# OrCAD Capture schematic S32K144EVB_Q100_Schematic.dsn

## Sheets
1 4. OpenSDA interface: size D; title: S32K144EVB-Q100; rev: C; company: Freescale Semiconductor; note: SCH-29248 PDF: SPF-29248; note: 6501 William Cannon Drive West; note: Austin, TX 78735-8598
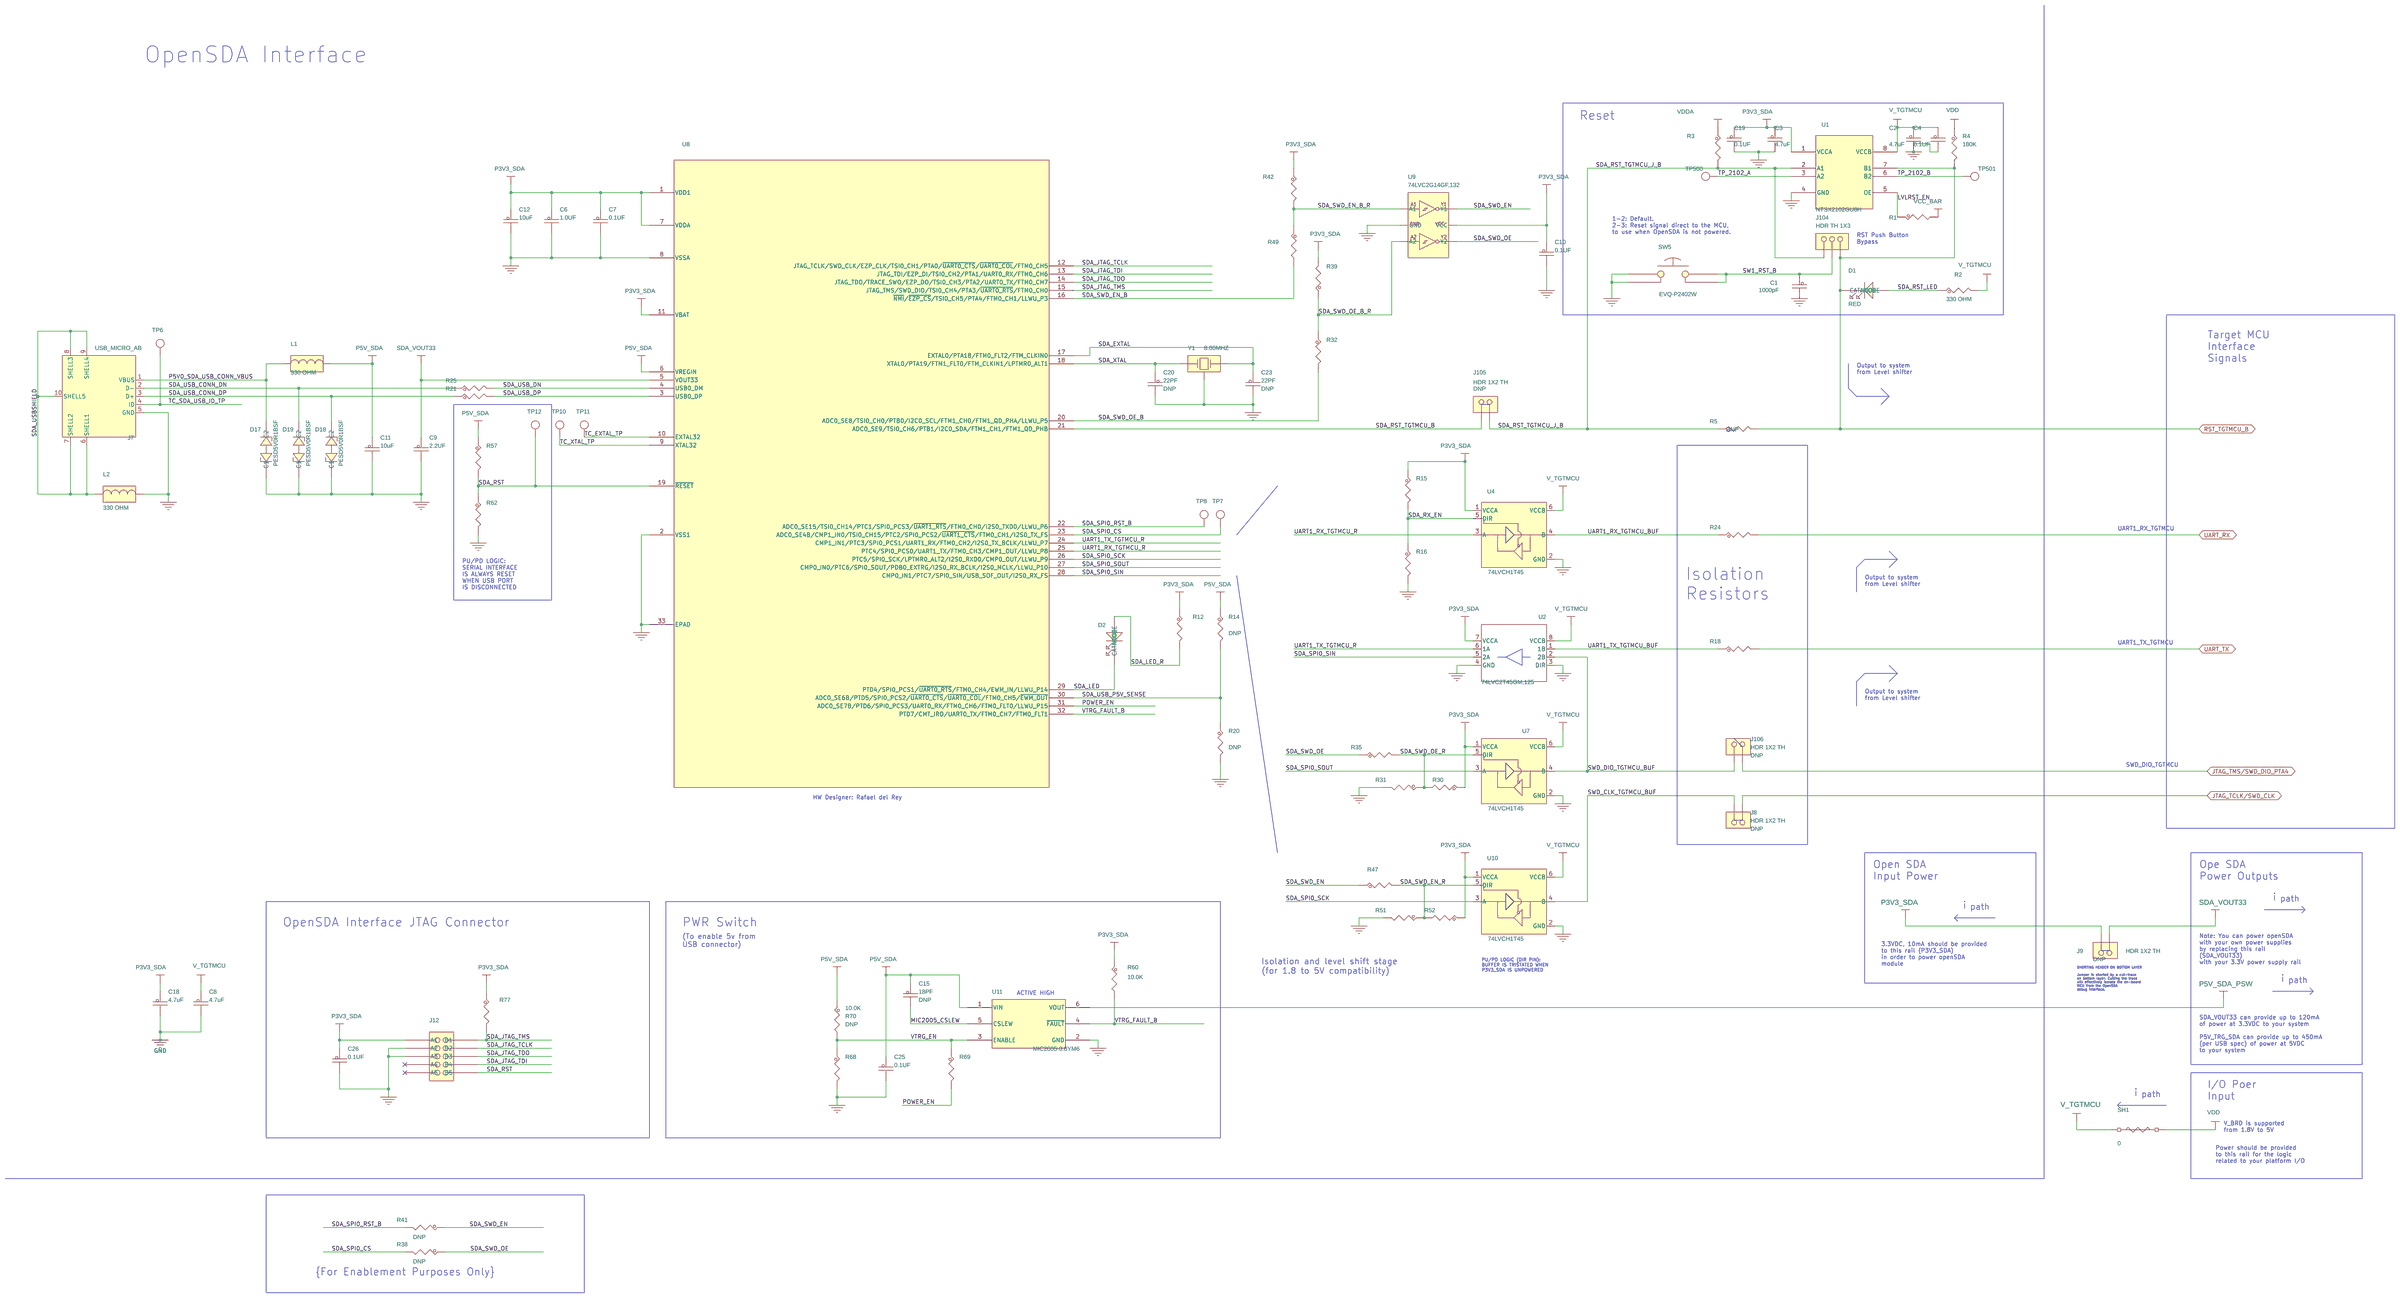
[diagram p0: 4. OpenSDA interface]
2 3. S32K144 MCU: size D; company: NXP Semiconductors
3 2. Notes and Block Diagram: company: NXP Semiconductors
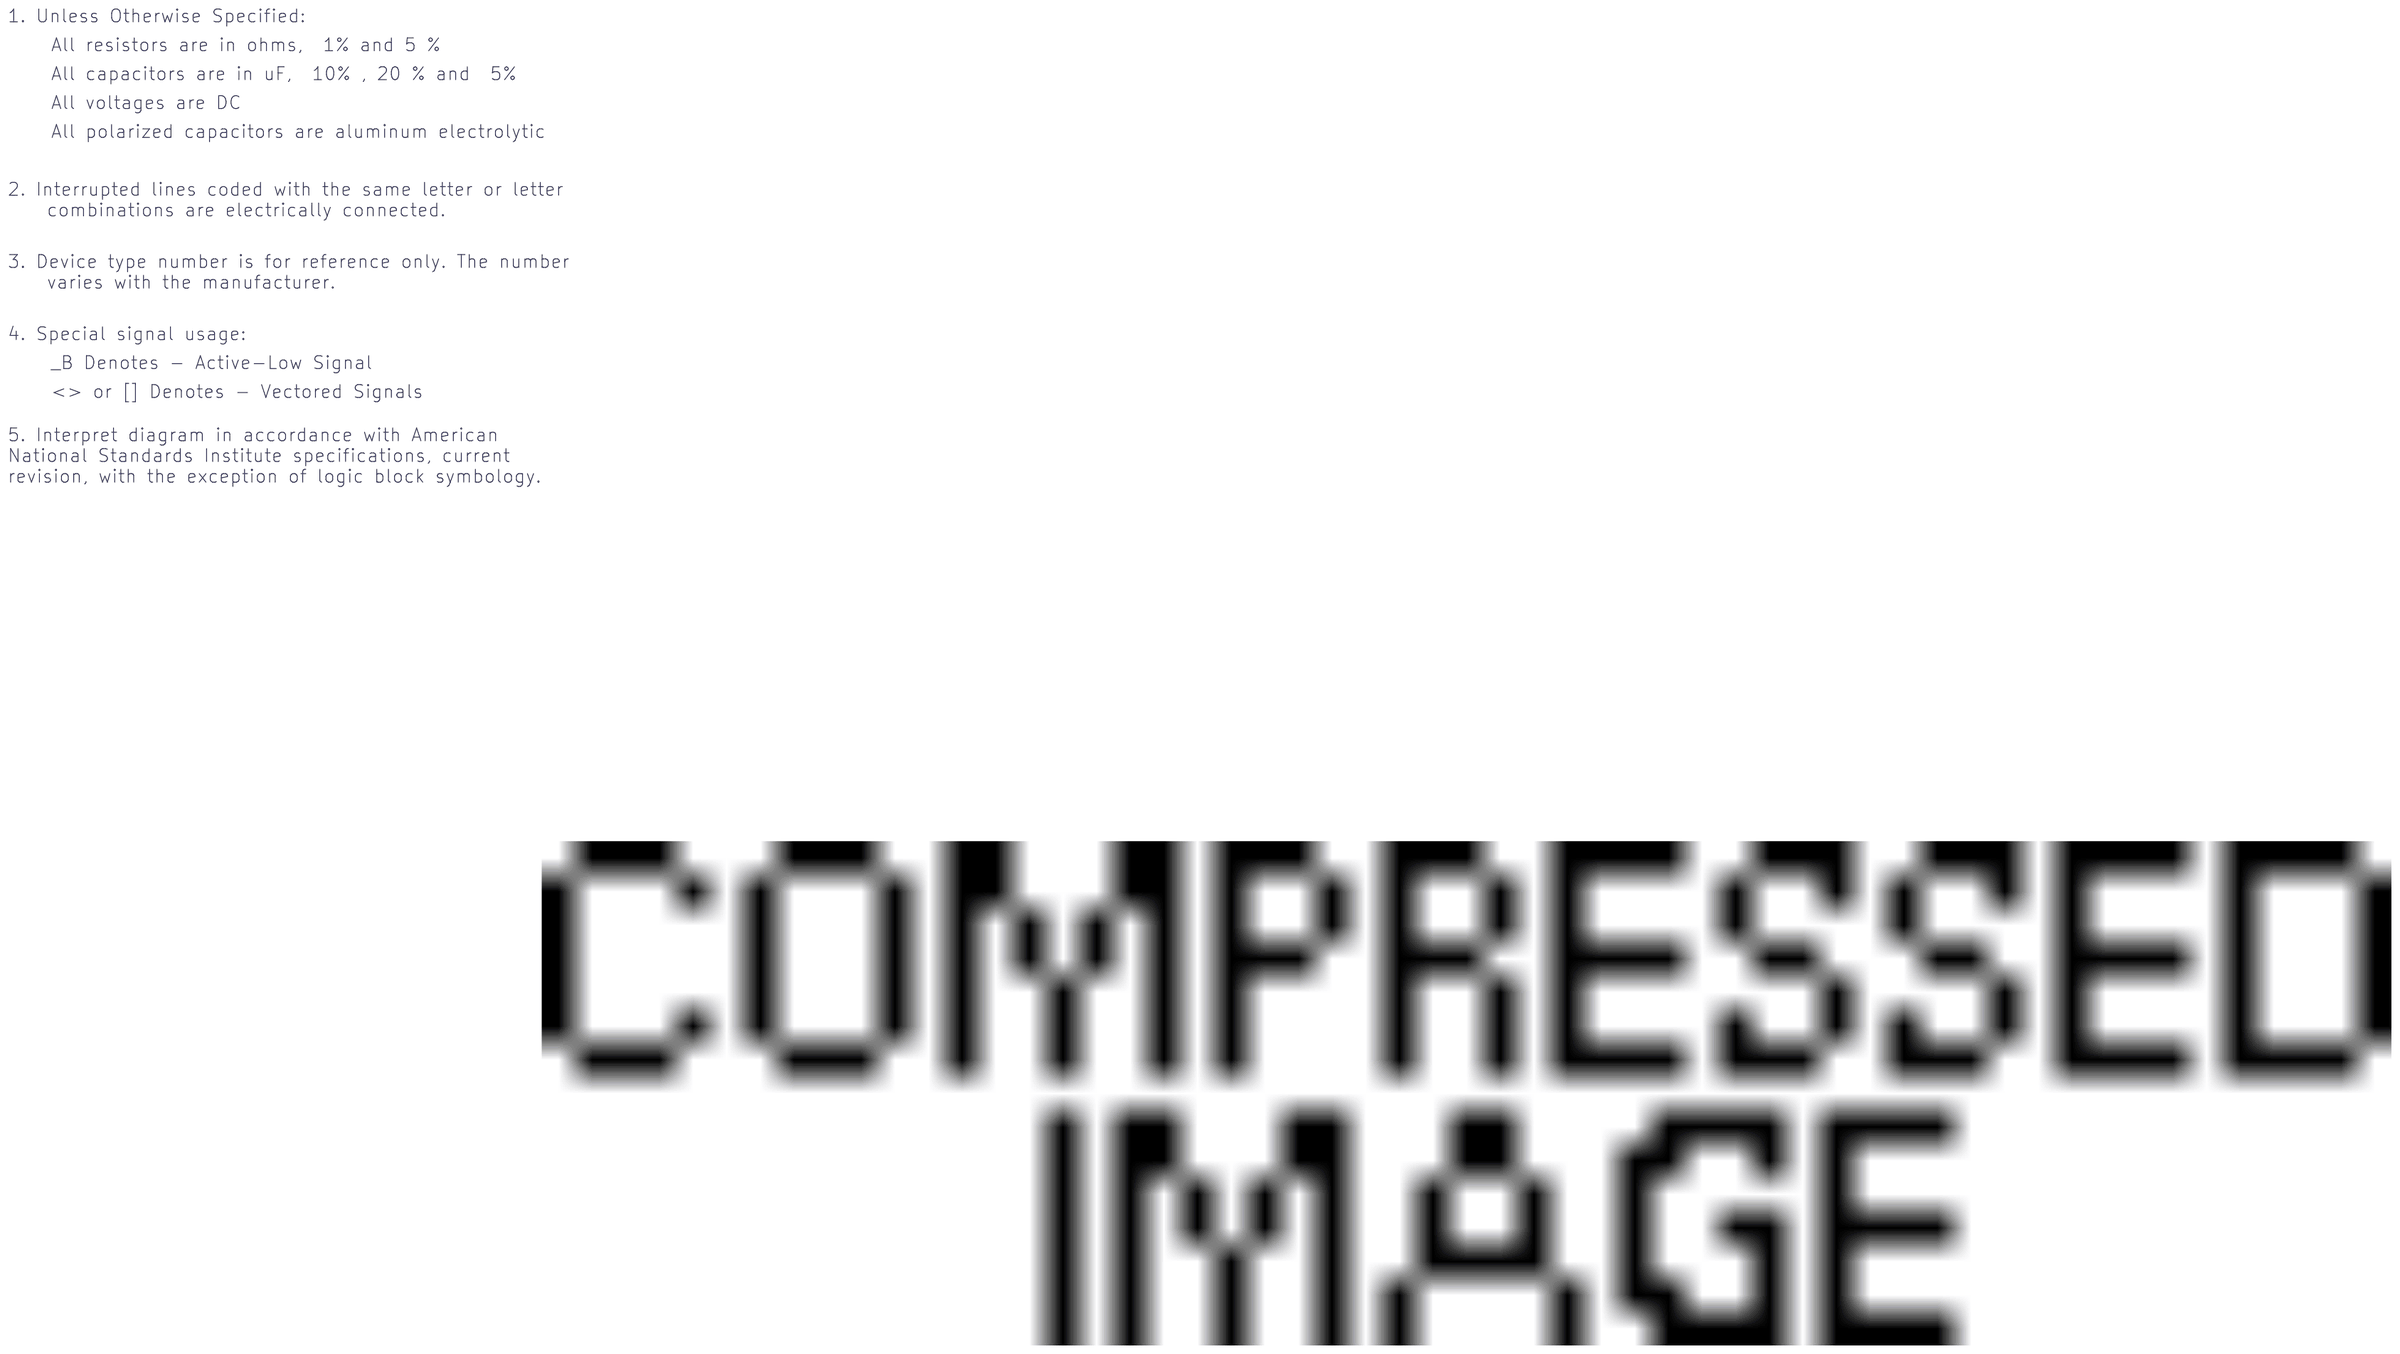
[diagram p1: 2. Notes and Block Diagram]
4 1. Title Page: company: NXP Semiconductors
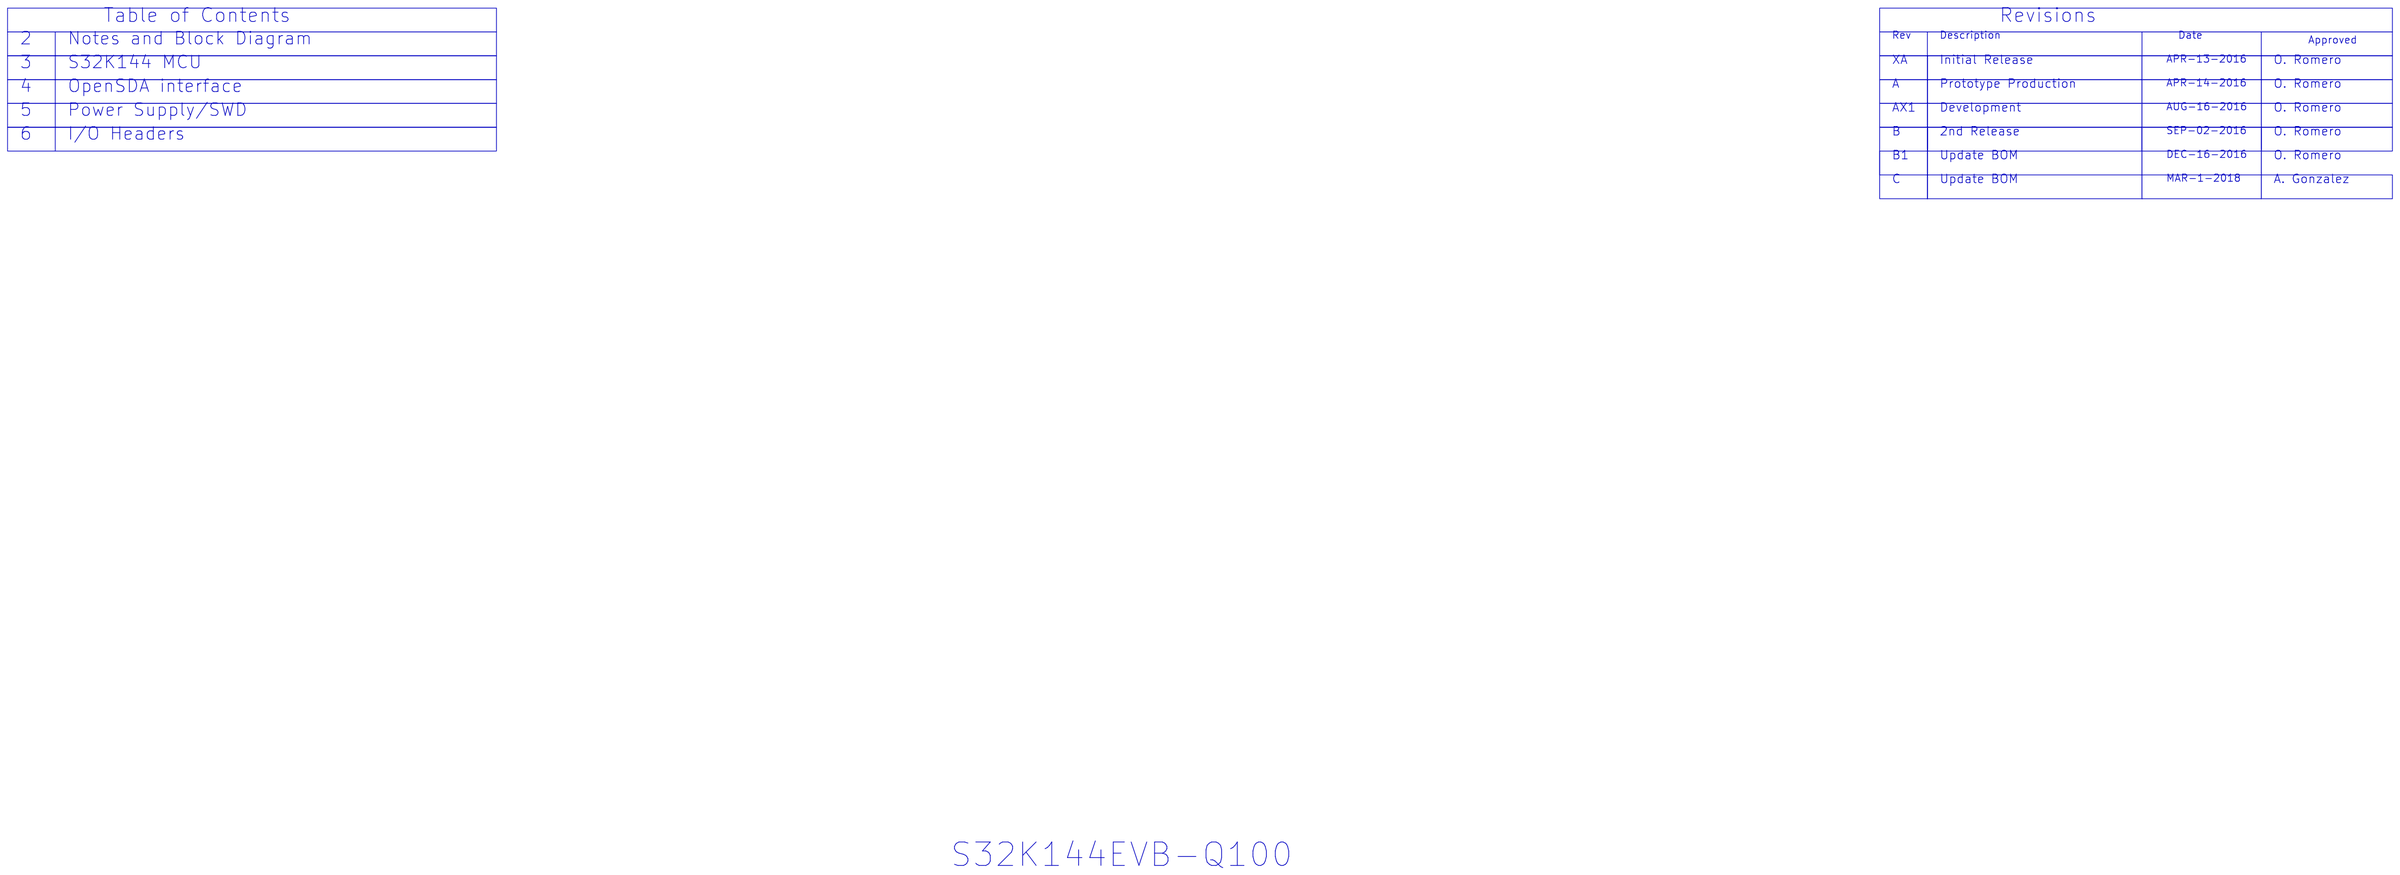
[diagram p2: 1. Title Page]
5 5. Power Supply/SWD: size C
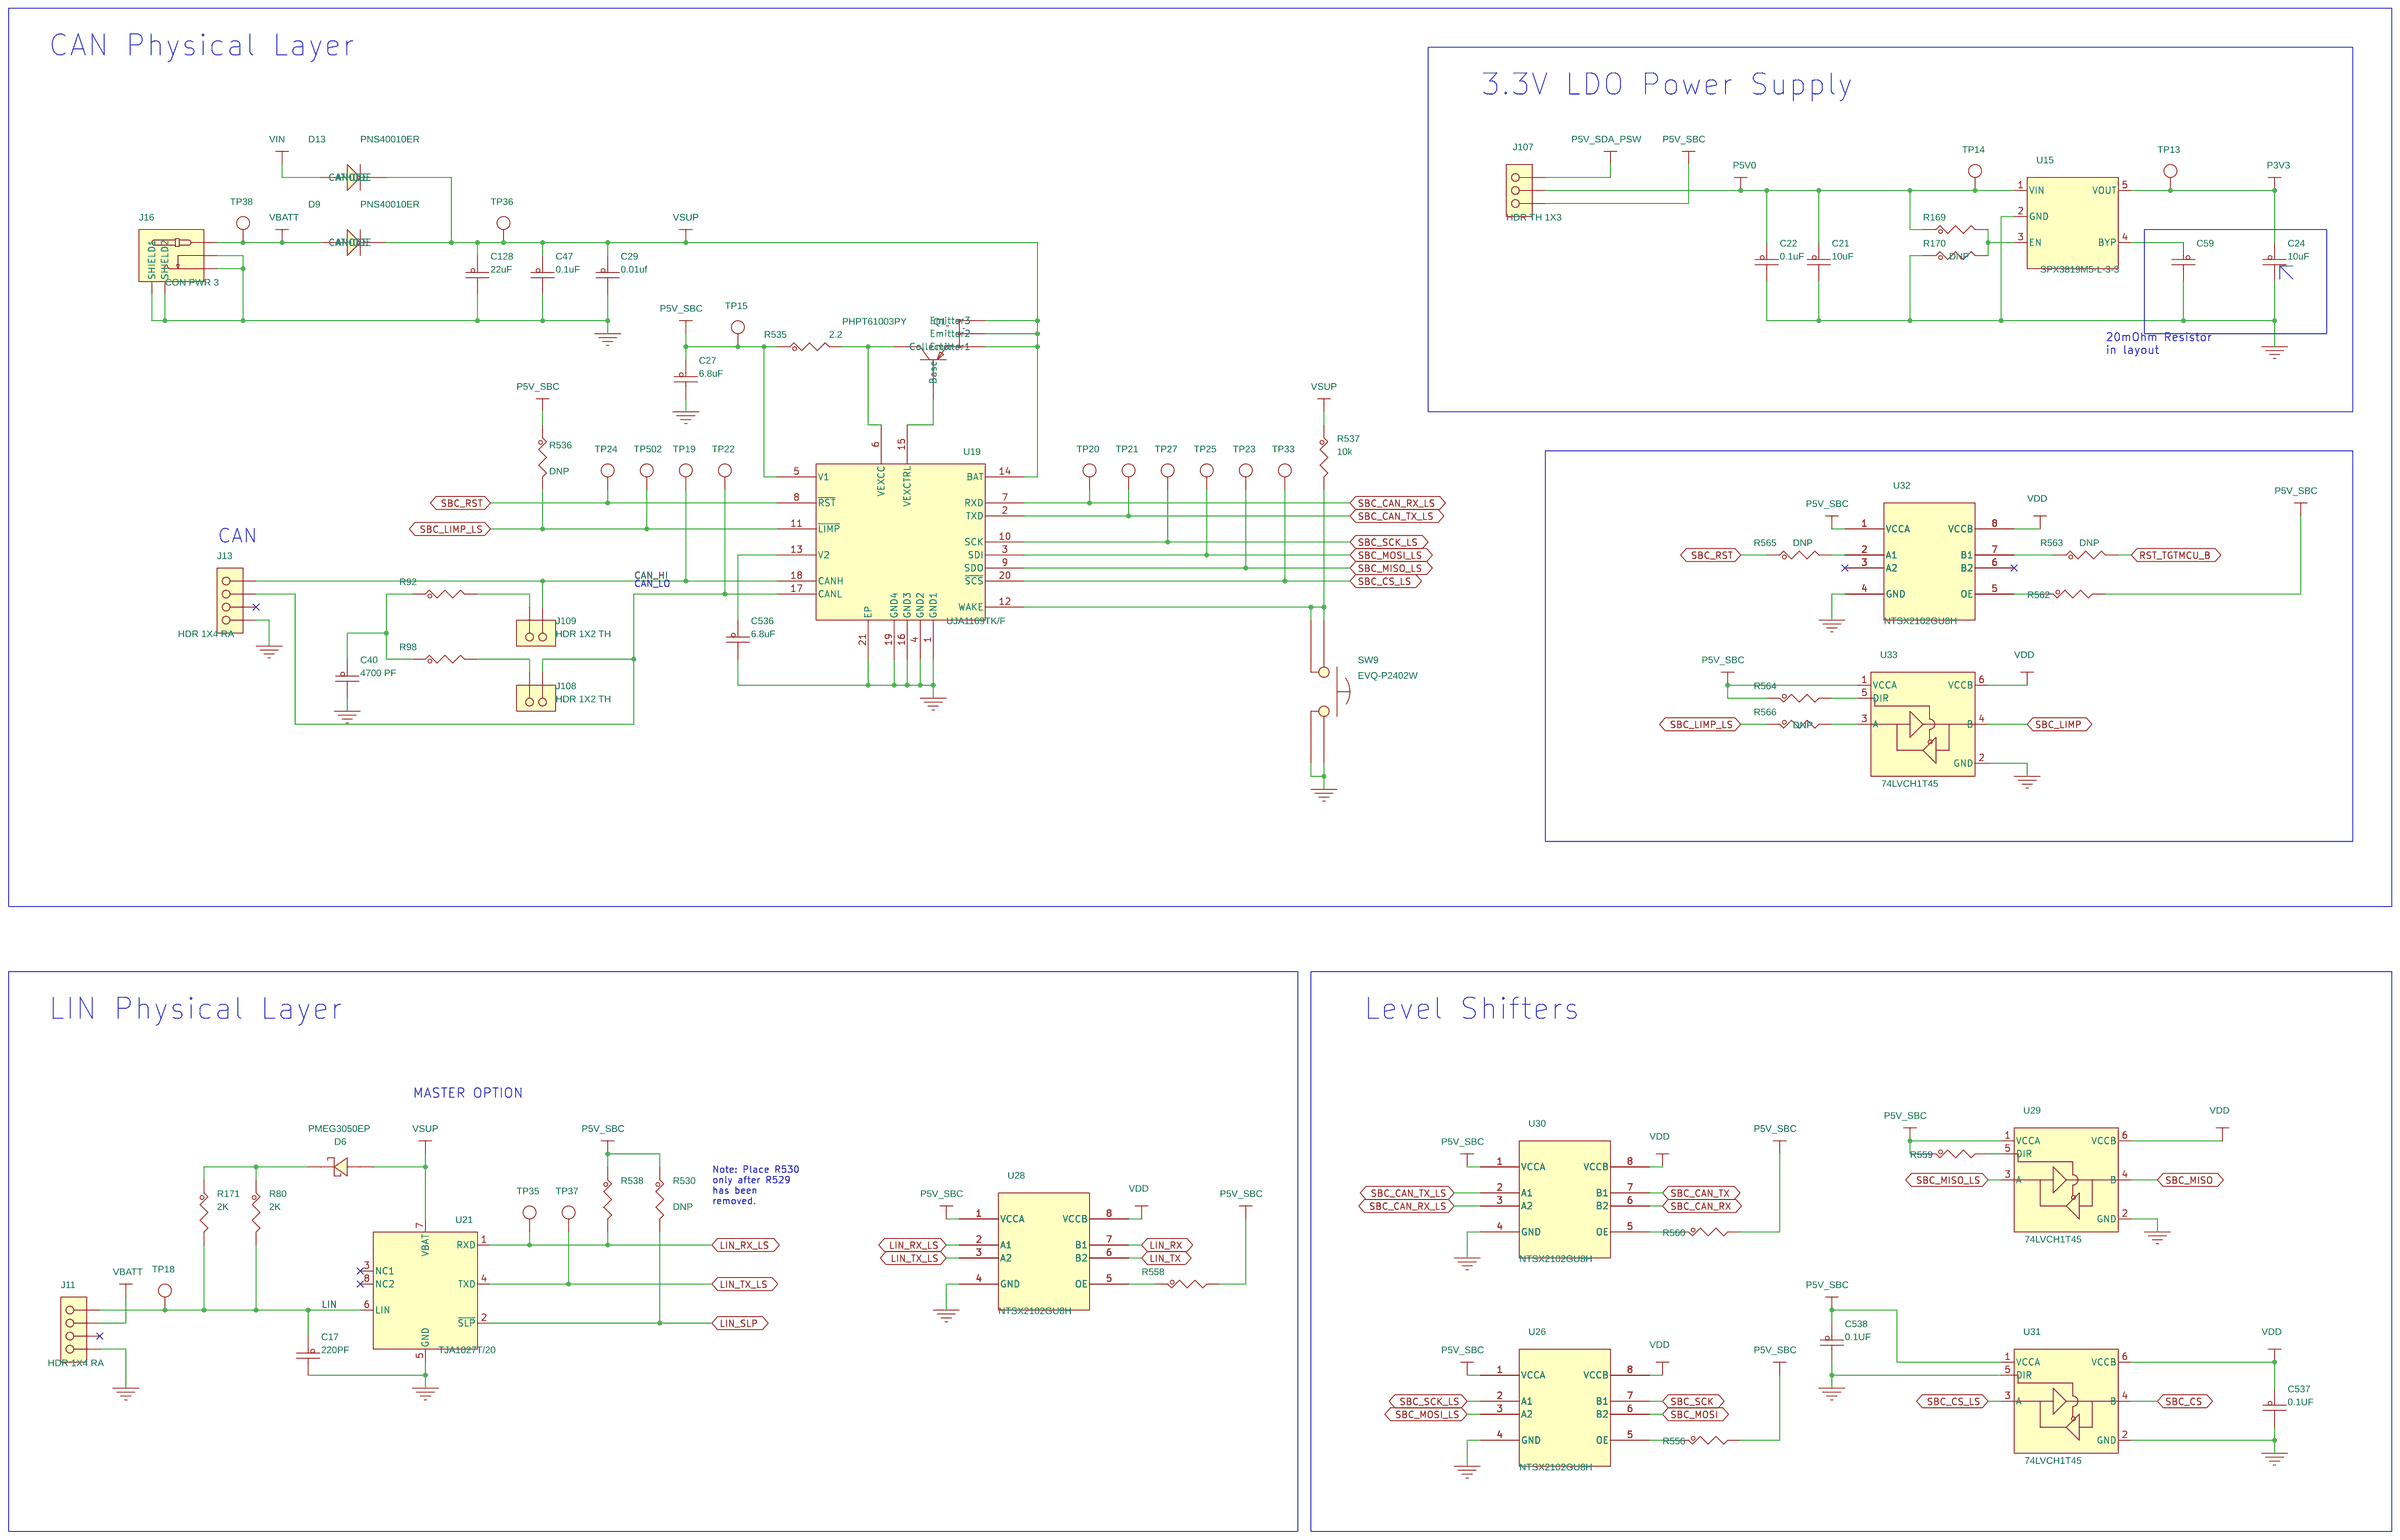
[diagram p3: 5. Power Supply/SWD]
6 6. I/O Headers: size C
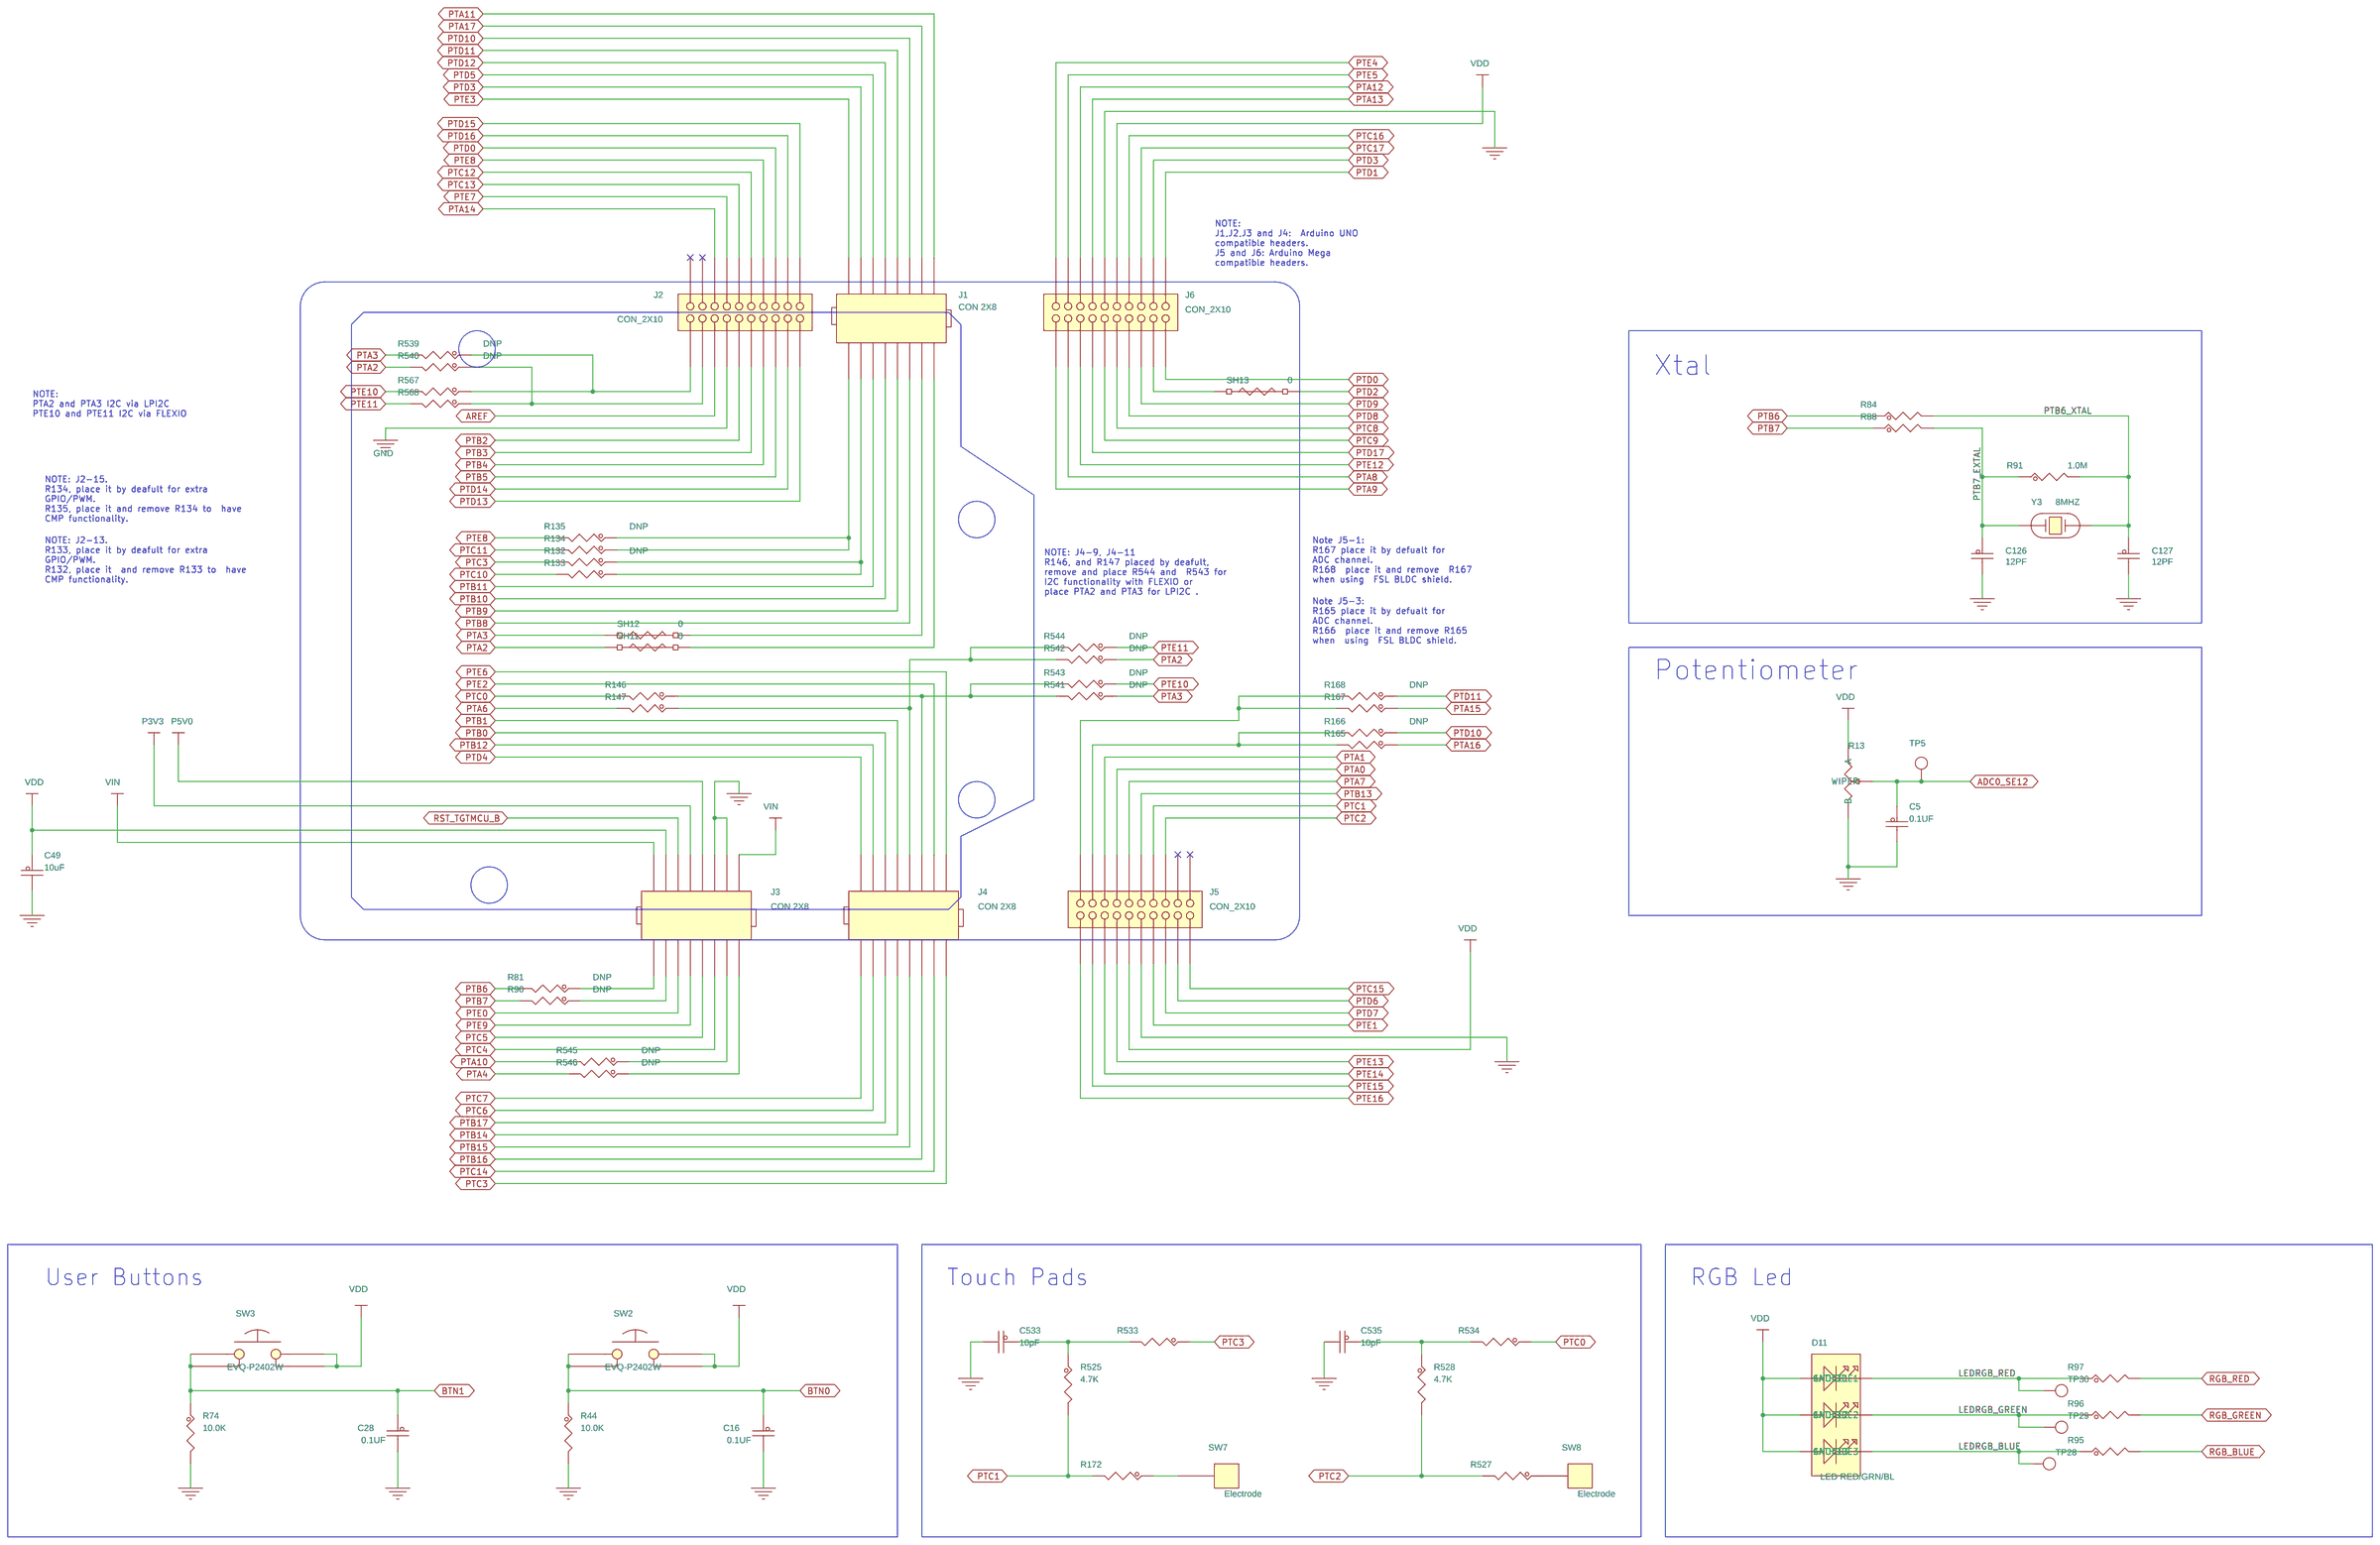
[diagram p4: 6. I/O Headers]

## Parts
sheet 3. S32K144 MCU
C43  10uF  [CC0603_OV]
C129  10uF  [CC0603_OV]
C131  10uF  [CC0603_OV]
C133  1UF  [CC0603_OV]
C137  1UF  [CC0603_OV]
C140  0.1uF  [CC0402_25]
C141  0.1uF  [CC0402_25]
C142  0.1uF  [CC0402_25]
C143  0.1uF  [CC0402_25]
C144  0.1uF  [CC0402_25]
C145  0.1uF  [CC0402_25]
C146  1UF  [CC0603_OV]
C147  1000PF  [CC0603_OV]
C148  0.1uF  [CC0402_25]
D3  GREEN  [LED_0603]
D7  BZX384-C30  [sod323]
J10  HDR TH 1X3  [HDR103]
J14  HDR 2X5  [CON_2RH_10_50]
J15  HDR 1X2 TH  [HDR102]
R56  330  [RC0603_OV]
R63  0  [RC0603_OV]
R64  0  [RC0603_OV]
R99  1K  [RC0603_OV]
R103  0  [RC0603_OV]
R109  0  [RC0603_OV]
R117  0  [RC0603_OV]
R119  0  [RC0603_OV]
R120  0  [RC0603_OV]
R121  10K  [RC0603_OV]
R122  0  [RC0603_OV]
R123  0  [RC0603_OV]
R124  0  [RC0603_OV]
R125  0  [RC0603_OV]
R126  0  [RC0603_OV]
R127  0  [RC0603_OV]
R128  0  [RC0603_OV]
R129  0  [RC0603_OV]
R130  0  [RC0603_OV]
R131  0  [RC0603_OV]
R136  0  [RC0603_OV]
R137  0  [RC0603_OV]
R152  0  [RC0603_OV]
R153  0  [RC0603_OV]
R154  0  [RC0603_OV]
R155  0  [RC0603_OV]
R156  0  [RC0603_OV]
R161  0  [RC0603_OV]
R162  0  [RC0603_OV]
R164  0  [RC0603_OV]
R529  0  [RC0603_OV]
R532  0  [RC0603_OV]
TP1  TEST POINT BLACK  [TEST_LOOP]
TP4  TEST POINT BLACK  [TEST_LOOP]
TP9  TEST POINT BLACK  [TEST_LOOP]
TP16  TEST POINT BLACK  [TEST_LOOP]
TP17  TEST POINT BLACK  [TEST_LOOP]
TP31  TPAD_030  [TPAD_030]
TP32  TEST POINT BLACK  [TEST_LOOP]
TP34  TPAD_030  [TPAD_030]
U17  PS32K144HFT0VLLT  [LQFP100_0P5_14X14]
sheet 4. OpenSDA interface
C1  1000pF  [CC0402_25]
C2  4.7uF  [CC0402_25]
C3  4.7uF  [CC0402_25]
C4  0.1UF  [CC0402_25]
C6  1.0UF  [CC0402_25]
C7  0.1UF  [CC0402_25]
C8  4.7uF  [CC0402_25]
C9  2.2UF  [CC0603_OV]
C10  0.1UF  [CC0402_25]
C11  10uF  [CC0402_25]
C12  10uF  [CC0603_OV]
C15  18PF  [CC0603_OV]
C18  4.7uF  [CC0402_25]
C19  0.1UF  [CC0402_25]
C20  22PF  [CC0402_25]
C23  22PF  [CC0402_25]
C25  0.1UF  [CC0402_25]
C26  0.1UF  [CC0402_25]
D1  RED  [LED_0603]
D2  LED GREEN  [LED_0603]
D17  PESD5V0R1BSF  [dsn0603-2]
D18  PESD5V0R1BSF  [dsn0603-2]
D19  PESD5V0R1BSF  [dsn0603-2]
J7  USB_MICRO_AB  [con_microab_10f_25_sm_ra]
J8  HDR 1X2 TH  [SH_HDR102_BOTTOM]
J9  HDR 1X2 TH  [SH_HDR102_BOTTOM]
J12  HDR 2X5  [CON_2RH_10_50]
J104  HDR TH 1X3  [HDR103]
J105  HDR 1X2 TH  [SH_HDR102_BOTTOM]
J106  HDR 1X2 TH  [SH_HDR102_BOTTOM]
L1  330 OHM  [ind_1608]
L2  330 OHM  [ind_1608]
R1  4.7K  [RC0402_25]
R2  330 OHM  [RC0402_25]
R3  10.0K  [RC0402_25]
R4  180K  [RC0402_25]
R5  0  [RC0402_25]
R12  220  [RC0603_OV]
R14  4.7K  [RC0402_25]
R15  4.7K  [RC0402_25]
R16  10.0K  [RC0402_25]
R18  0  [RC0402_25]
R20  10.0K  [RC0402_25]
R21  33  [RC0402_25]
R24  0  [RC0402_25]
R25  33  [RC0402_25]
R30  4.7K  [RC0402_25]
R31  10.0K  [RC0402_25]
R32  0  [RC0402_25]
R35  0  [RC0402_25]
R38  0  [RC0402_25]
R39  10.0K  [RC0402_25]
R41  0  [RC0402_25]
R42  10.0K  [RC0402_25]
R47  0  [RC0402_25]
R49  0  [RC0402_25]
R51  10.0K  [RC0402_25]
R52  4.7K  [RC0402_25]
R57  4.7K  [RC0402_25]
R60  10.0K  [RC0402_25]
R62  10.0K  [RC0402_25]
R68  15K  [RC0402_25]
R69  1.0K  [RC0402_25]
R70  10.0K  [RC0402_25]
R77  10.0K  [RC0402_25]
SH1  0  [SH0603]
SW5  EVQ-P2402W  [sw4_spst_4p8X3p6_2p5]
TP6  TPAD_030  [TPAD_030]
TP7  TPAD_030  [TPAD_030]
TP8  TPAD_030  [TPAD_030]
TP10  TPAD_030  [TPAD_030]
TP11  TPAD_030  [TPAD_030]
TP12  TPAD_030  [TPAD_030]
TP500  TPAD_030  [TPAD_030]
TP501  TPAD_030  [TPAD_030]
U1  NTSX2102GU8H  [xqfn8_1p45x1p25mm]
U2  74LVC2T45GM,125  [qfn8_1p6x1p6mm]
U4  74LVCH1T45  [udfn6_1x1p5mm]
U7  74LVCH1T45  [udfn6_1x1p5mm]
U8  MK20DX128VFM5  [QFN32_S142EP]
U9  74LVC2G14GF,132  [SOT891_6P_0P35_1P05X1P05]
U10  74LVCH1T45  [udfn6_1x1p5mm]
U11  MIC2005-0.8YM6  [SOT23-6_a]
Y1  8.00MHZ  [xtal3_3p35x1p45_sm]
sheet 5. Power Supply/SWD
C17  220PF  [CC0603_OV]
C21  10uF  [CC0603_OV]
C22  0.1uF  [CC0603_OV]
C24  10uF  [CC0603_OV]
C27  6.8uF  [CC0805_OV]
C29  0.01uf  [CC0603_OV]
C40  4700 PF  [CC0603_OV]
C47  0.1uF  [CC0603_OV]
C59  0.01UF  [CC0402_25]
C128  22uF  [CC0805_OV]
C536  6.8uF  [CC0805_OV]
C537  0.1UF  [CC0402_25]
C538  0.1UF  [CC0402_25]
D6  PMEG3050EP  [sod-128]
D9  PNS40010ER  [sod123w]
D13  PNS40010ER  [sod123w]
J11  HDR 1X4 RA  [con_hdr_4m_100_th_ra]
J13  HDR 1X4 RA  [con_hdr_4m_100_th_ra]
J16  CON PWR 3  [con3_pwr_jack_th_pj051a]
J107  HDR TH 1X3  [HDR103]
J108  HDR 1X2 TH  [HDR102]
J109  HDR 1X2 TH  [HDR102]
Q1  PHPT61003PY  [LFPAK5_1P27_5X4]
R80  2K  [RC0805_OV]
R92  60.4  [RC1206_OV]
R98  60.4  [RC1206_OV]
R169  0  [RC0402_25]
R170  0  [RC0402_25]
R171  2K  [RC0805_OV]
R530  4.7K  [RC0603_OV]
R535  2.2  [RC0805_OV]
R536  4.7K  [RC0603_OV]
R537  10k  [RC0805_OV]
R538  4.7K  [RC0603_OV]
R556  4.7K  [RC0402_25]
R558  4.7K  [RC0402_25]
R559  4.7K  [RC0402_25]
R560  4.7K  [RC0402_25]
R562  4.7K  [RC0402_25]
R563  0  [RC0603_OV]
R564  4.7K  [RC0402_25]
R565  0  [RC0603_OV]
R566  0  [RC0603_OV]
SW9  EVQ-P2402W  [sw4_spst_4p8X3p6_2p5]
TP13  TPAD_030  [TPAD_030]
TP14  TPAD_030  [TPAD_030]
TP15  TPAD_030  [TPAD_030]
TP18  TPAD_030  [TPAD_030]
TP19  TPAD_030  [TPAD_030]
TP20  TPAD_030  [TPAD_030]
TP21  TPAD_030  [TPAD_030]
TP22  TPAD_030  [TPAD_030]
TP23  TPAD_030  [TPAD_030]
TP24  TPAD_030  [TPAD_030]
TP25  TPAD_030  [TPAD_030]
TP27  TPAD_030  [TPAD_030]
TP33  TPAD_030  [TPAD_030]
TP35  TPAD_030  [TPAD_030]
TP36  TPAD_030  [TPAD_030]
TP37  TPAD_030  [TPAD_030]
TP38  TPAD_030  [TPAD_030]
TP502  TPAD_030  [TPAD_030]
U15  SPX3819M5-L-3-3  [SOT23_5S]
U19  UJA1169TK/F  [son20_0p5_3p6x5p6]
U21  TJA1027T/20  [so8_1p27_4x5]
U26  NTSX2102GU8H  [xqfn8_1p45x1p25mm]
U28  NTSX2102GU8H  [xqfn8_1p45x1p25mm]
U29  74LVCH1T45  [udfn6_1x1p5mm]
U30  NTSX2102GU8H  [xqfn8_1p45x1p25mm]
U31  74LVCH1T45  [udfn6_1x1p5mm]
U32  NTSX2102GU8H  [xqfn8_1p45x1p25mm]
U33  74LVCH1T45  [udfn6_1x1p5mm]
sheet 6. I/O Headers
C5  0.1UF  [CC0402_25]
C16  0.1UF  [CC0402_25]
C28  0.1UF  [CC0402_25]
C49  10uF  [CC0603_OV]
C126  12PF  [CC0402_25]
C127  12PF  [CC0402_25]
C533  10pF  [CC0603_OV]
C535  10pF  [CC0603_OV]
D11  LED RED/GRN/BL  [led6_5x6mm]
J1  CON 2X8  [con_skt2x8_th]
J2  CON_2X10  [con2x10_2p54_th]
J3  CON 2X8  [con_skt2x8_th]
J4  CON 2X8  [con_skt2x8_th]
J5  CON_2X10  [con2x10_2p54_th]
J6  CON_2X10  [con2x10_2p54_th]
R13  5K  [pot3_3352t]
R44  10.0K  [RC0402_25]
R74  10.0K  [RC0402_25]
R81  0  [RC0603_OV]
R84  0  [RC0603_OV]
R88  0  [RC0603_OV]
R90  0  [RC0603_OV]
R91  1.0M  [RC0603_OV]
R95  220  [RC0603_OV]
R96  220  [RC0603_OV]
R97  220  [RC0603_OV]
R132  0  [RC0603_OV]
R133  0  [RC0603_OV]
R134  0  [RC0603_OV]
R135  0  [RC0603_OV]
R146  0  [RC0603_OV]
R147  0  [RC0603_OV]
R165  0  [RC0603_OV]
R166  0  [RC0603_OV]
R167  0  [RC0603_OV]
R168  0  [RC0603_OV]
R172  0  [RC0603_OV]
R525  4.7K  [RC0603_OV]
R527  0  [RC0603_OV]
R528  4.7K  [RC0603_OV]
R533  0  [RC0603_OV]
R534  0  [RC0603_OV]
R539  0  [RC0603_OV]
R540  0  [RC0603_OV]
R541  0  [RC0603_OV]
R542  0  [RC0603_OV]
R543  0  [RC0603_OV]
R544  0  [RC0603_OV]
R545  0  [RC0603_OV]
R546  0  [RC0603_OV]
R567  0  [RC0603_OV]
R568  0  [RC0603_OV]
SH11  0  [SH0603]
SH12  0  [SH0603]
SH13  0  [SH0603]
SW2  EVQ-P2402W  [sw4_spst_4p8X3p6_2p5]
SW3  EVQ-P2402W  [sw4_spst_4p8X3p6_2p5]
SW7  Electrode  [electrode_sq_15mm]
SW8  Electrode  [electrode_sq_15mm]
TP5  TPAD_030  [TPAD_030]
TP28  TPAD_030  [TPAD_030]
TP29  TPAD_030  [TPAD_030]
TP30  TPAD_030  [TPAD_030]
Y3  8MHZ  [xtal2_3p3x2p6]

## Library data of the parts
C43 C49 C129 C131 = CAP_NP: CAP CER 10uF 10V 20% X7R 0603; AGILE_PN: 150-80120; CAD_APPROVED: Yes; FPLIST: CC0603_OV,CC0603,0603_CC; HEIGHT: 1MM; MFG_NAME01: MURATA; MFG_PN01: GRM188Z71A106MA73; ROHS: Yes; Temp_Range: -55°C to +125°C; Tolerance: 20%; VOLTAGE: 10V
C133 C137 C146 = CAP_NP: CAP CER 1.0UF 10V 10% X7R 0603; AGILE_PN: 150-78462; ASSY_OPT: DNP; CAD_APPROVED: Yes; FPLIST: CC0603_OV,CC0603,0603_CC; HEIGHT: 0.9MM; MFG_NAME01: MURATA; MFG_PN01: GRM188R71A105KA61D; ROHS: Yes; Tolerance: 10%; VOLTAGE: 10V
C140-C145 C148 = CAP_NP: CAP CER 0.1UF 10V 10% X7R 0402; AGILE_PN: 150-30217; CAD_APPROVED: Yes; FPLIST: CC0402_25,CC0402_HD,CC0402_SQ,0402_CC; HEIGHT: 0.55 MM; MFG_NAME01: SMEC; MFG_PN01: MCCB104K0NRTF; ROHS: Yes; Tolerance: 10%; VOLTAGE: 10V
C147 = CAP_NP: CAP CER 1000PF 100V 10% X7R 0603; AGILE_PN: 150-77156; ASSY_OPT: DNP; CAD_APPROVED: Yes; FPLIST: CC0603_OV,CC0603,0603_CC; HEIGHT: 0.95MM; MFG_NAME01: KEMET; MFG_PN01: C0603C102K1RACTU; ROHS: Yes; Tolerance: 10%; VOLTAGE: 100V
D3 = LED: LED GRN SGL 25MA 0603; AGILE_PN: 370-76549; CAD_APPROVED: Yes; HEIGHT: 0.85MM; MFG_NAME01: KINGBRIGHT; MFG_PN01: KPT-1608SGC; ROHS: Yes
D7 = ZDIODE: DIODE ZNR 30V 300mW SOD323; AGILE_PN: 480-78597; ASSY_OPT: DNP; CAD_APPROVED: Yes; HEIGHT: 1.1MM; MFG_NAME01: NEXPERIA; MFG_PN01: BZX384-C30,115; ROHS: Yes
J10 = CONN_HDR_3X1: HDR 1X3 TH 100MIL SP 339H AU 100L; AGILE_PN: 210-75726; ASSY_OPT: DNP; CAD_APPROVED: Yes; HEIGHT: 8.65MM; MFG_NAME01: SAMTEC; MFG_PN01: TSW-103-07-G-S; ROHS: Yes
J12 J14 = CONN_HDR_5X2: CONN,HEAD,2X5,STR,50/50 CON-2RH-10-50; AGILE_PN: 210-07961-00; CAD_APPROVED: Yes; FPLIST: CON_2RH_10_50,con_2rh_10_50_nsp; HEIGHT: 3.91 MM; MFG_NAME01: SAMTEC; MFG_PN01: FTS-105-01-F-D; ROHS: Yes
J15 = CONN_HDR_2X1: HDR 1X2 TH 100MIL SP 339H AU 98L; AGILE_PN: 210-75439; ASSY_OPT: DNP; CAD_APPROVED: YES; FPLIST: HDR102,SH_HDR102_BOTTOM; HEIGHT: 8.71 MM; MFG_NAME01: SAMTEC; MFG_PN01: TSW-102-07-G-S; ROHS: Yes
R56 = RES: RES MF 330 OHM 1/10W 1% 0603; AGILE_PN: 470-75512; CAD_APPROVED: Yes; FPLIST: RC0603_OV,RC0603,0603_CC; HEIGHT: 0.55 MM; MFG_NAME01: BOURNS; MFG_PN01: CR0603-FX-3300ELF; ROHS: Yes; Tolerance: 1%
R63 R81 R90 R109 R132 R135 R166 R168 R539-R546 R563 R565 R566 = RES: RES MF ZERO OHM 1/10W -- AEC-Q200 0603; AGILE_PN: 470-75407; ASSY_OPT: DNP; CAD_APPROVED: Yes; FPLIST: RC0603_OV,RC0603,R603-X2,0603_CC; HEIGHT: 0.6MM; MFG_NAME01: PANASONIC; MFG_PN01: ERJ-3GEY0R00V; ROHS: Yes; Tolerance: 1%
R64 R84 R88 R103 R117 R119 R120 R122-R131 R133 R134 R136 R137 R146 R147 R152-R156 R161 R162 R164 R165 R167 R172 R527 R529 R532-R534 R567 R568 = RES: RES MF ZERO OHM 1/10W -- AEC-Q200 0603; AGILE_PN: 470-75407; CAD_APPROVED: Yes; FPLIST: RC0603_OV,RC0603,R603-X2,0603_CC; HEIGHT: 0.6MM; MFG_NAME01: PANASONIC; MFG_PN01: ERJ-3GEY0R00V; ROHS: Yes; Tolerance: 1%
R99 = RES: RES MF 1.0K 1/10W 5% 0603; AGILE_PN: 470-75412; ASSY_OPT: DNP; CAD_APPROVED: YES; FPLIST: RC0603_OV,RC0603,0603_CC; HEIGHT: 0.6MM; MFG_NAME01: VENKEL COMPANY; MFG_PN01: CR0603-10W-102JT; ROHS: Yes; SIGNAL_MODEL: DEFAULT_RESISTOR_1000.000000OHM_2_1; Tolerance: 5%
R121 = RES: RES MF 10K 1/10W 0.1% AEC-Q200 0603; AGILE_PN: 470-80764; CAD_APPROVED: Yes; FPLIST: RC0603_OV,RC0603,0603_CC; HEIGHT: 0.55MM; MFG_NAME01: Vishay Intertechnology; MFG_PN01: TNPW060310K0BEEN; ROHS: Yes; Tolerance: 0.1%
TP1 TP4 TP9 TP16 TP17 TP32 = TestLoop: TEST POINT BLACK 40 MIL DRILL 180 MIL TH 109L; AGILE_PN: 210-75683; ASSY_OPT: DNP; CAD_APPROVED: Yes; HEIGHT: 4.8mm; MFG_NAME01: KEYSTONE ELECTRONICS; MFG_PN01: 5001; ROHS: Yes
TP5-TP8 TP10-TP15 TP18-TP25 TP27-TP31 TP33-TP38 TP500-TP502 = TestLoop: TEST POINT PAD 30MIL DIA SMT, NO PART TO ORDER; AGILE_PN: 211-76642; CAD_APPROVED: Yes; HEIGHT: 0.1MM; MFG_NAME01: NOTACOMPONENT; MFG_PN01: NOTACOMPONENT; ROHS: Yes
U17 = PS32K144_LQFP_3: IC MCU 512K FLASH 2.7-5.5V 112MHZ LQFP100; AGILE_PN: 344-02148; CAD_APPROVED: Yes; HEIGHT: 1.7 MM; MFG_NAME01: FREESCALE SEMICONDUCTOR; ROHS: Yes
C1 = CAP_NP: CAP CER 1000PF 50V 5% C0G 0402; AGILE_PN: 150-76334; CAD_APPROVED: Yes; FPLIST: CC0402_25,CC0402_HD,0402_CC; HEIGHT: 0.55MM; MFG_NAME01: MURATA; MFG_PN01: GRM1555C1H102JA01D; ROHS: Yes; Tolerance: 5%; VOLTAGE: 50V
C2 C3 C8 C18 = CAP_NP: CAP CER 4.7UF 6.3V 20% X5R 0402; AGILE_PN: 150-78463; CAD_APPROVED: Yes; FPLIST: CC0402_25,CC0402_HD,0402_CC; HEIGHT: 0.65MM; MFG_NAME01: TDK; MFG_PN01: C1005X5R0J475M050BC; PRIORITY_PN: 021-00169; ROHS: Yes; SIGNAL_MODEL: DEFAULT_CAPACITOR_4.7e+06pF_2_1; TOL: 10%; Tolerance: 20%; VOLTAGE: 6.3V
C4 C7 C10 C19 C25 C26 C537 C538 = CAP_NP: CAP CER 0.1UF 10V 10% X5R 0402; AGILE_PN: 150-75634; CAD_APPROVED: Yes; FPLIST: CC0402_25,CC0402_HD,0402_CC; HEIGHT: 0.64MM; MFG_NAME01: KEMET; MFG_PN01: C0402C104K8PAC; PRIORITY_PN: 021-00169; ROHS: Yes; SIGNAL_MODEL: DEFAULT_CAPACITOR_100000pF_2_1; TOL: 10%; Tolerance: 10%; VOLTAGE: 10V
C6 = CAP_NP: CAP CER 1.0UF 10V 10% X5R 0402; AGILE_PN: 150-75772; CAD_APPROVED: Yes; FPLIST: CC0402_25,CC0402_HD,0402_CC; HEIGHT: 0.6MM; MFG_NAME01: YAGEO AMERICA; MFG_PN01: CC0402KRX5R6BB105; PRIORITY_PN: 021-00242; ROHS: Yes; SIGNAL_MODEL: DEFAULT_CAPACITOR_1e+06pF_2_1; VOLTAGE: 10V
C9 = CAP_NP: CAP CER 2.2UF 10V 10% X7R 0603; AGILE_PN: 150-78564; CAD_APPROVED: Yes; FPLIST: CC0603_OV,CC0603,0603_CC; HEIGHT: 1.25MM; MFG_NAME01: TAIYO YUDEN; MFG_PN01: LMK107B7225KA-T; ROHS: Yes; SIGNAL_MODEL: DEFAULT_CAPACITOR_2.2e+06pF_2_1; Tolerance: 10%; VOLTAGE: 10V
C11 = CAP_NP: CAP CER 10uF 10V 20% X5R 0402; AGILE_PN: 150-79255; CAD_APPROVED: Yes; FPLIST: C0402_25,CC0402_HD,0402_CC; HEIGHT: 0.7MM; MFG_NAME01: NIC COMPONENTS CORP; MFG_PN01: NMC0402X5R106M10TRPF; PRIORITY_PN: 021-00242; ROHS: Yes; SIGNAL_MODEL: DEFAULT_CAPACITOR_1e+06pF_2_1; Tolerance: 20%; VOLTAGE: 10V
C12 = CAP_NP: CAP CER 10uF 16V 20% X5R 0603; AGILE_PN: 150-79092; CAD_APPROVED: Yes; FPLIST: CC0603_OV,CC0603,0603_CC; HEIGHT: 1mm; MFG_NAME01: TAIYO YUDEN; MFG_PN01: EMK107BBJ106MA-T; ROHS: Yes; SIGNAL_MODEL: DEFAULT_CAPACITOR_1e+07pF_2_1; TOL: 10%; Tolerance: 20%; VOLTAGE: 16V
C15 = CAP_NP: CAP CER 18PF 50V 5% C0G 0603; AGILE_PN: 150-75116; ASSY_OPT: DNP; CAD_APPROVED: Yes; FPLIST: CC0603_OV,CC0603,0603_CC; HEIGHT: 0.90MM; MFG_NAME01: YAGEO AMERICA; MFG_PN01: CC0603JRNPO9BN180; PRIORITY_PN: 021-00320; ROHS: Yes; SIGNAL_MODEL: DEFAULT_CAPACITOR_18.000000pF_2_1; TOL: 5%; Tolerance: 5%; VOLTAGE: 50V
C20 C23 = CAP_NP: CAP CER 22PF 50V 5% C0G 0402; AGILE_PN: 150-75266; ASSY_OPT: DNP; CAD_APPROVED: Yes; FPLIST: CC0402_25,CC0402_HD,0402_CC; HEIGHT: 0.635MM; MFG_NAME01: AVX; MFG_PN01: 04025A220JAT2A; PRIORITY_PN: 021-00234; ROHS: Yes; SIGNAL_MODEL: DEFAULT_CAPACITOR_22.000000pF_2_1; Tolerance: 5%; VOLTAGE: 50V
D1 = LED: LED ULTRA BRIGHT RED SGL 30MA 0603; AGILE_PN: 370-75079; CAD_APPROVED: Yes; HEIGHT: 0.9MM; MFG_NAME01: LITE ON; MFG_PN01: LTST-C190KRKT; ROHS: Yes
D2 = LED: LED GRN SGL 20MA 0603; AGILE_PN: 370-76565; CAD_APPROVED: Yes; HEIGHT: 0.67MM; MFG_NAME01: osram; MFG_PN01: LG L29K-G2J1-24-Z; ROHS: Yes
D17-D19 = DIODE_BIDIR: DIODE TVS 5VWM 9.2VC DSN0603-2; AGILE_PN: 480-79664; CAD_APPROVED: Yes; HEIGHT: 0.32MM; MFG_NAME01: NEXPERIA; MFG_PN01: PESD5V0R1BSFYL; ROHS: Yes
J7 = MICRO_USB_CONN_10PIN: CON 5 USB_MICRO_AB_RECEPTACLE RA SKT SMT 0.65MM SP 122H AU; AGILE_PN: 211-78945; CAD_APPROVED: Yes; HEIGHT: 3.1MM; MFG_NAME01: molex; MFG_PN01: 0475900001; ROHS: Yes
J8 J9 J105 J106 = CONN_HDR_2X1: HDR 1X2 TH 100MIL SP 339H AU 98L; AGILE_PN: 210-75439; ASSY_OPT: DNP; CAD_APPROVED: YES; FPLIST: HDR102,SH_HDR102_BOTTOM; HEIGHT: 8.71 MM; MFG_NAME01: SAMTEC; MFG_PN01: TSW-102-07-G-S; PRIORITY_PN: 028-00556; ROHS: Yes
J104 J107 = CONN_HDR_3X1: HDR 1X3 TH 100MIL SP 339H AU 100L; AGILE_PN: 210-75726; CAD_APPROVED: Yes; HEIGHT: 8.65MM; MFG_NAME01: SAMTEC; MFG_PN01: TSW-103-07-G-S; ROHS: Yes
L1 L2 = BEAD: IND FER BEAD 330OHM@100MHZ 1.7A 0603; AGILE_PN: 180-78156; CAD_APPROVED: Yes; FPLIST: ind_1608,0603_CC; HEIGHT: 0.95MM; MFG_NAME01: TDK; MFG_PN01: MPZ1608S331A; PART_TYPE: FERRITE\BEAD; ROHS: Yes; Tolerance: 25%
R1 R15 R30 R52 R57 R556 R558-R560 R562 R564 = RES: RES MF 4.7K 1/16W 5% 0402; AGILE_PN: 470-75626; CAD_APPROVED: Yes; FPLIST: RC0402_25,RC0402_HD,0402_CC; HEIGHT: 0.41mm; MFG_NAME01: NIC COMPONENTS CORP; MFG_PN01: NRCL04J472TRF; ROHS: Yes; SIGNAL_MODEL: DEFAULT_RESISTOR_4700OHM_2_1; TOL: 1%; Tolerance: 5%
R2 = RES: RES MF 330 OHM 1/16W 1% 0402; AGILE_PN: 470-80566; CAD_APPROVED: Yes; FPLIST: RC0402_25,RC0402_HD,0402_CC; HEIGHT: 0.4MM; MFG_NAME01: WALSIN TECHNOLOGY CORP.; MFG_PN01: WR04X3300FTL; ROHS: Yes; Tolerance: 1%
R3 R16 R31 R39 R42 R51 = RES: RES MF 10.0K 1/16W 1% AEC-Q200 0402; AGILE_PN: 470-75416; CAD_APPROVED: Yes; FPLIST: RC0402_25,RC0402_HD,0402_CC; HEIGHT: 0.4MM; MFG_NAME01: KOA SPEER; MFG_PN01: RK73H1ETTP1002F; PRIORITY_PN: 006-00552; ROHS: Yes; SIGNAL_MODEL: DEFAULT_RESISTOR_10000OHM_2_1; TOL: 5%; Tolerance: 1%
R4 = RES: RES MF 180K 1/10W 1% AEC-Q200 0402; AGILE_PN: 470-31088; CAD_APPROVED: Yes; FPLIST: RC0402_25,RC0402_HD,0402_CC; HEIGHT: 0.40 MM; MFG_NAME01: KOA SPEER; MFG_PN01: RK73H1ETTP1803F; ROHS: Yes; SIGNAL_MODEL: DEFAULT_RESISTOR_180000OHM_2_1; Temp_Range: -55C to +155C; Tolerance: 1%
R5 = RES: RES MF ZERO OHM 1/16W -- AEC-Q200 0402; AGILE_PN: 470-80742; ASSY_OPT: DNP; CAD_APPROVED: Yes; FPLIST: RC0402_25,RC0402_HD,0402_CC; HEIGHT: 0.45 MM; MFG_NAME01: VISHAY INTERTECHNOLOGY; MFG_PN01: CRCW04020000Z0ED; PRIORITY_PN: 006-00559; ROHS: Yes; SIGNAL_MODEL: DEFAULT_RESISTOR_0.001OHM_2_1; TOL: 5%; VOLTAGE: 1/16W
R12 = RES: RES MF 220 OHM 1/10W 5% 0603; AGILE_PN: 470-30297; CAD_APPROVED: Yes; FPLIST: RC0603_OV,RC0603,0603_CC; HEIGHT: 0.6MM; MFG_NAME01: YAGEO AMERICA; MFG_PN01: RC0603JR-07220RL; ROHS: Yes; SIGNAL_MODEL: DEFAULT_RESISTOR_220.000000OHM_2_1; Tolerance: 5%
R14 = RES: RES MF 4.7K 1/16W 5% 0402; AGILE_PN: 470-75626; ASSY_OPT: DNP; CAD_APPROVED: Yes; FPLIST: RC0402_25,RC0402_HD,0402_CC; HEIGHT: 0.41mm; MFG_NAME01: NIC COMPONENTS CORP; MFG_PN01: NRCL04J472TRF; ROHS: Yes; SIGNAL_MODEL: DEFAULT_RESISTOR_4700OHM_2_1; TOL: 1%; Tolerance: 5%
R18 R24 = RES: RES MF ZERO OHM 1/16W -- AEC-Q200 0402; AGILE_PN: 470-80742; CAD_APPROVED: Yes; FPLIST: RC0402_25,RC0402_HD,0402_CC; HEIGHT: 0.45 MM; MFG_NAME01: VISHAY INTERTECHNOLOGY; MFG_PN01: CRCW04020000Z0ED; PRIORITY_PN: 006-00559; ROHS: Yes; SIGNAL_MODEL: DEFAULT_RESISTOR_0.001OHM_2_1; TOL: 5%; VOLTAGE: 1/16W
R20 = RES: RES MF 10.0K 1/16W 1% AEC-Q200 0402; AGILE_PN: 470-75416; ASSY_OPT: DNP; CAD_APPROVED: Yes; FPLIST: RC0402_25,RC0402_HD,0402_CC; HEIGHT: 0.4MM; MFG_NAME01: KOA SPEER; MFG_PN01: RK73H1ETTP1002F; PRIORITY_PN: 006-00552; ROHS: Yes; SIGNAL_MODEL: DEFAULT_RESISTOR_10000OHM_2_1; Tolerance: 1%
R21 R25 = RES: RES MF 33.0 OHM 1/16W 1% 0402; AGILE_PN: 470-75790; CAD_APPROVED: Yes; FPLIST: RC0402_25,RC0402_HD,RC0402_X2,0402_CC; HEIGHT: 0.4MM; MFG_NAME01: THYE MING TECH CO LTD; MFG_PN01: CR-02FL6---33R; PRIORITY_PN: 006-00556; ROHS: Yes; SIGNAL_MODEL: DEFAULT_RESISTOR_33.000000OHM_2_1; Tolerance: 1%
R32 R35 R47 R49 = RES: RES MF ZERO OHM 1/16W -- AEC-Q200 0402; AGILE_PN: 470-80742; CAD_APPROVED: Yes; FPLIST: RC0402_25,RC0402_HD,0402_CC; HEIGHT: 0.45 MM; MFG_NAME01: VISHAY INTERTECHNOLOGY; MFG_PN01: CRCW04020000Z0ED; PRIORITY_PN: 006-00559; ROHS: Yes; SIGNAL_MODEL: DEFAULT_RESISTOR_0.001OHM_2_1; VOLTAGE: 1/16W
R38 R41 = RES: RES MF ZERO OHM 1/16W -- AEC-Q200 0402; AGILE_PN: 470-80742; ASSY_OPT: DNP; CAD_APPROVED: Yes; FPLIST: RC0402_25,RC0402_HD,0402_CC; HEIGHT: 0.45 MM; MFG_NAME01: VISHAY INTERTECHNOLOGY; MFG_PN01: CRCW04020000Z0ED; PRIORITY_PN: 006-00559; ROHS: Yes; SIGNAL_MODEL: DEFAULT_RESISTOR_0.001OHM_2_1; VOLTAGE: 1/16W
R44 R60 R74 = RES: RES MF 10.0K 1/16W 1% AEC-Q200 0402; AGILE_PN: 470-75416; CAD_APPROVED: Yes; FPLIST: RC0402_25,RC0402_HD,0402_CC; HEIGHT: 0.4MM; MFG_NAME01: KOA SPEER; MFG_PN01: RK73H1ETTP1002F; PRIORITY_PN: 006-00552; ROHS: Yes; SIGNAL_MODEL: DEFAULT_RESISTOR_10000OHM_2_1; TOL: 1%; Tolerance: 1%
R62 R77 = RES: RES MF 10.0K 1/16W 1% AEC-Q200 0402; AGILE_PN: 470-75416; CAD_APPROVED: Yes; FPLIST: RC0402_25,RC0402_HD,0402_CC; HEIGHT: 0.4MM; MFG_NAME01: KOA SPEER; MFG_PN01: RK73H1ETTP1002F; PRIORITY_PN: 006-00552; ROHS: Yes; SIGNAL_MODEL: DEFAULT_RESISTOR_10000OHM_2_1; Tolerance: 1%
R68 = RES: RES MF 15K  1/16W 1% 0402; AGILE_PN: 470-30965; CAD_APPROVED: Yes; FPLIST: RC0402_25,RC0402_HD,0402_CC; HEIGHT: 0.40 MM; MFG_NAME01: WALSIN TECHNOLOGY CORP.; MFG_PN01: WR04X1502FTL; ROHS: Yes; SIGNAL_MODEL: DEFAULT_RESISTOR_15000OHM_2_1; TOL: 1%; Tolerance: 1%
R69 = RES: RES MF 1.0K 1/16W 1% 0402; AGILE_PN: 470-76037; CAD_APPROVED: Yes; FPLIST: RC0402_25,RC0402_HD,RC0402_X2,0402_CC; HEIGHT: 0.4MM; MFG_NAME01: YAGEO AMERICA; MFG_PN01: RC0402FR-071KL; PRIORITY_PN: 006-00553; ROHS: Yes; SIGNAL_MODEL: DEFAULT_RESISTOR_1000.000000OHM_2_1; TOL: 1%; Tolerance: 1%; VOLTAGE: 1/16W
R70 = RES: RES MF 10.0K 1/16W 1% AEC-Q200 0402; AGILE_PN: 470-75416; ASSY_OPT: DNP; CAD_APPROVED: Yes; FPLIST: RC0402_25,RC0402_HD,0402_CC; HEIGHT: 0.4MM; MFG_NAME01: KOA SPEER; MFG_PN01: RK73H1ETTP1002F; PRIORITY_PN: 006-00552; ROHS: Yes; SIGNAL_MODEL: DEFAULT_RESISTOR_10000OHM_2_1; TOL: 1%; Tolerance: 1%
SH1 SH11-SH13 = RES_SHORT-2: ZERO OHM CUT TRACE 0603 PADS; NO PART TO ORDER; AGILE_PN: 470-80018; CAD_APPROVED: Yes; FPLIST: SH0603,SH0603_CC,SH0603-X2_PIN1TO2,SH0603-X2_PIN2TO3; HEIGHT: 0.1MM; MFG_NAME01: LAYOUT ELEMENT ONLY; MFG_PN01: LAYOUT ELEMENT ONLY; ROHS: Yes; SIGNAL_MODEL: DEFAULT_RESISTOR_0.001OHM_2_1
SW2 SW3 SW5 SW9 = EDGE_MOUNT_PB_SW_2: SW SPST PB NO 0.02A 15V SMT; AGILE_PN: 510-77992; CAD_APPROVED: Yes; HEIGHT: 2.7 MM; MFG_NAME01: Panasonic; ROHS: Yes
U1 U26 U28 U30 U32 = NTSX2102GU8H_8P: IC DUAL SUPPLY XCVR 50 MBPS 5.5V XQFN8; AGILE_PN: 312-80763; CAD_APPROVED: Yes; HEIGHT: 0.5MM; MFG_NAME01: NXP Semiconductors; ROHS: Yes; VOLTAGE: 5.5V
U2 = 74LVC2T45GM_8P: IC XCVR DUAL SUPPLY 1.2 -5.5V XQFN8; AGILE_PN: 312-80762; CAD_APPROVED: Yes; HEIGHT: 0.5MM; MFG_NAME01: NEXPERIA; ROHS: Yes; VOLTAGE: 5.5V
U4 U7 U10 U29 U31 U33 = 74LVCH1T45_6P: IC XCVR 1BIT 3-STATE DUAL 1.2-5.5V XSON6; AGILE_PN: 312-80758; CAD_APPROVED: Yes; HEIGHT: 0.5MM; MFG_NAME01: NEXPERIA; MFG_PN01: 74LVCH1T45GM,132; ROHS: Yes; VOLTAGE: 1.2-5.5V
U8 = PK20DX128V_QFN_32P: IC MCU FLASH 128KB 50MHZ 1.71-3.6V QFN32; AGILE_PN: 344-01231; CAD_APPROVED: Yes; HEIGHT: 1MM; MFG_NAME01: FREESCALE SEMICONDUCTOR; ROHS: Yes; VOLTAGE: 1.71-3.6V
U9 = NC7WP14: IC DUAL INV SCHMITT-TRIG 1.65-5.5V  XSON6; AGILE_PN: 315-80930; CAD_APPROVED: Yes; HEIGHT: 0.5MM; MFG_NAME01: NEXPERIA; ROHS: Yes
U11 = MIC2005-0.8YM6: IC LIN SW PWR 0.8A 2.5-5.5V SOT23-6; AGILE_PN: 315-79199; CAD_APPROVED: Yes; HEIGHT: 1.45MM; MFG_NAME01: MICREL; PRIORITY_PN: 051-MIC2005-08; ROHS: Yes; VOLTAGE: 2.5-5.5V
Y1 = XTAL_CS: XTAL 8.00MHZ RSN CERAMIC -- SMT; AGILE_PN: 230-77664; CAD_APPROVED: Yes; HEIGHT: 0.8MM; MFG_NAME01: MURATA; MFG_PN01: CSTCE8M00G55-R0; PRIORITY_PN: 048-00290; ROHS: Yes
C17 = CAP_NP: CAP CER 220PF 50V 10% X7R 0603; AGILE_PN: 150-75200; CAD_APPROVED: Yes; FPLIST: CC0603_OV,CC0603,0603_CC; HEIGHT: 0.9652MM; MFG_NAME01: KEMET; MFG_PN01: C0603C221K5RAC; ROHS: Yes; Tolerance: 10%; VOLTAGE: 50V
C21 = CAP_NP: CAP CER 10uF 25V 20% X5R 0603; AGILE_PN: 150-79272; CAD_APPROVED: Yes; FPLIST: CC0603_OV,CC0603,0603_CC; HEIGHT: 1MM; MFG_NAME01: Murata; MFG_PN01: GRM188R61E106MA73D; ROHS: Yes; SIGNAL_MODEL: DEFAULT_CAPACITOR_1e+07pF_2_1; Tolerance: 20%; VOLTAGE: 25V
C22 = CAP_NP: CAP CER 0.1uF 50V 10% X7R AEC-Q200 0603; AGILE_PN: 150-79042; CAD_APPROVED: Yes; FPLIST: CC0603_OV,CC0603,0603_CC; HEIGHT: 0.9 MM; MFG_NAME01: MURATA; MFG_PN01: GCM188R71H104KA57D; ROHS: Yes; Tolerance: 10%; VOLTAGE: 50V
C24 = CAP_NP: CAP CER 10uF 16V 20% X5R 0603; AGILE_PN: 150-79092; CAD_APPROVED: Yes; FPLIST: CC0603_OV,CC0603,0603_CC; HEIGHT: 1mm; MFG_NAME01: TAIYO YUDEN; MFG_PN01: EMK107BBJ106MA-T; ROHS: Yes; SIGNAL_MODEL: DEFAULT_CAPACITOR_1e+07pF_2_1; Tolerance: 20%; VOLTAGE: 16V
C27 C536 = CAP_NP: CAP CER 6.8uF 16V 10% X7S AEC-Q200 0805; AGILE_PN: 150-79536; CAD_APPROVED: Yes; FPLIST: CC0805_OV,CC0805,0805_CC; HEIGHT: 1.45MM; MFG_NAME01: TDK; MFG_PN01: CGA4J1X7S1C685K125AC; ROHS: Yes; Tolerance: 10%; VOLTAGE: 16V
C29 = CAP_NP: CAP CER 0.01uF 50V 10% X7R AEC-Q200 0603; AGILE_PN: 150-79361; CAD_APPROVED: Yes; FPLIST: CC0603_OV,CC0603,0603_CC; HEIGHT: 0.9MM; MFG_NAME01: TDK; MFG_PN01: CGA3E2X7R1H103K080AA; ROHS: Yes; Tolerance: 10%; VOLTAGE: 50V
C40 = CAP_NP: CAP CER 4700PF 50V 5% X7R 0603; AGILE_PN: 150-30045; CAD_APPROVED: Yes; FPLIST: CC0603_OV,CC0603,0603_CC; HEIGHT: 1.0MM; MFG_NAME01: AVX; MFG_PN01: 06035C472JAT2A; ROHS: Yes; Tolerance: 5%; VOLTAGE: 50V
C47 = CAP_NP: CAP CER 0.1uF 25V 10% X8R 0603; AGILE_PN: 150-78955; CAD_APPROVED: Yes; FPLIST: CC0603_OV,CC0603,0603_CC; HEIGHT: 0.9 MM; MFG_NAME01: TDK; MFG_PN01: C1608X8R1E104K080AA; ROHS: Yes; Temp_Range: -55 C to +150 C; Tolerance: 10%; VOLTAGE: 25V
C59 = CAP_NP: CAP CER 0.01UF 16V 20% X7R 0402; AGILE_PN: 150-30082; CAD_APPROVED: Yes; FPLIST: CC0402_25,CC0402_HD,0402_CC; HEIGHT: 0.56MM; MFG_NAME01: AVX; MFG_PN01: 0402YC103MAT2A; ROHS: Yes; TOL: 20%; Tolerance: 20%; VOLTAGE: 16V
C128 = CAP_NP: CAP CER 22uF 25V 20% X5R AEC-Q200 0805; AGILE_PN: 150-79697; CAD_APPROVED: Yes; FPLIST: CC0805_OV,CC0805,0805_CC; HEIGHT: 1.45MM; MFG_NAME01: MURATA; MFG_PN01: GRT21BR61E226ME13; ROHS: Yes; Tolerance: 20%; VOLTAGE: 25V
D6 = DIODE_SCHTKY: DIODE SCH RECT 5A 30V AEC-Q101 SOD128; AGILE_PN: 480-78776; CAD_APPROVED: Yes; HEIGHT: 1.1 MM; MFG_NAME01: NEXPERIA; MFG_PN01: PMEG3050EP,115; ROHS: Yes
D9 D13 = DIODE: DIODE RECT SW 1A 400V AEC-Q101 SOD123W; AGILE_PN: 480-79648; CAD_APPROVED: Yes; HEIGHT: 1.1MM; MFG_NAME01: NEXPERIA; MFG_PN01: PNS40010ER,115; ROHS: Yes
J11 J13 = CONN_HDR_4X1: HDR 1X4 TH RA 100MIL SP 268H AU 124L; AGILE_PN: 210-79929; CAD_APPROVED: Yes; HEIGHT: 6.81MM; MFG_NAME01: MOLEX; MFG_PN01: 0022122041; ROHS: Yes
J16 = DC_POWER_JACK_SHD: CON 3 PWR JACK RA TH 295H -- NI 98L; AGILE_PN: 210-79945; CAD_APPROVED: Yes; HEIGHT: 7.5MM; MFG_NAME01: CUI INC; MFG_PN01: PJ-051A; ROHS: Yes
J108 J109 = CONN_HDR_2X1: HDR 1X2 TH 100MIL SP 339H AU 98L; AGILE_PN: 210-75439; CAD_APPROVED: YES; FPLIST: HDR102,SH_HDR102_BOTTOM; HEIGHT: 8.71 MM; MFG_NAME01: SAMTEC; MFG_PN01: TSW-102-07-G-S; ROHS: Yes
Q1 = PMOS_5P: TRAN PNP PWR 3A 100V AEC-Q101 LFPAK56; AGILE_PN: 480-79653; CAD_APPROVED: Yes; HEIGHT: 1.2 MM; MFG_NAME01: NEXPERIA; MFG_PN01: PHPT61003PYX; ROHS: Yes
R80 R171 = RES: RES MF 2K 1/8W 1% 0805; AGILE_PN: 470-76341; CAD_APPROVED: Yes; FPLIST: RC0805_OV,RC0805,0805_CC; HEIGHT: 0.65MM; MFG_NAME01: BOURNS; MFG_PN01: CR0805-FX-2001ELF; ROHS: Yes; Tolerance: 1%
R92 R98 = RES: RES MF 60.4 OHM 1/4W 1% 1206; AGILE_PN: 470-78243; CAD_APPROVED: Yes; FPLIST: RC1206_OV,RC1206,1206_CC; HEIGHT: 0.6MM; MFG_NAME01: VISHAY INTERTECHNOLOGY; MFG_PN01: CRCW120660R4FKEA; ROHS: Yes; Tolerance: 1%
R169 = RES: RES MF ZERO OHM 1/16W -- AEC-Q200 0402; AGILE_PN: 470-80742; CAD_APPROVED: Yes; FPLIST: RC0402_25,RC0402_HD,0402_CC; HEIGHT: 0.45 MM; MFG_NAME01: VISHAY INTERTECHNOLOGY; MFG_PN01: CRCW04020000Z0ED; ROHS: Yes
R170 = RES: RES MF ZERO OHM 1/16W -- AEC-Q200 0402; AGILE_PN: 470-80742; ASSY_OPT: DNP; CAD_APPROVED: Yes; FPLIST: RC0402_25,RC0402_HD,0402_CC; HEIGHT: 0.45 MM; MFG_NAME01: VISHAY INTERTECHNOLOGY; MFG_PN01: CRCW04020000Z0ED; ROHS: Yes
R530 R536 = RES: RES MF 4.7K 1/10W 5% 0603; AGILE_PN: 470-75414; ASSY_OPT: DNP; CAD_APPROVED: Yes; FPLIST: RC0603_OV,RC0603,0603_CC; HEIGHT: 0.55 MM; MFG_NAME01: VISHAY INTERTECHNOLOGY; MFG_PN01: CRCW06034K70JNEA; ROHS: Yes; Tolerance: 5%
R535 = RES: RES MF 2.20 OHM 1/8W 1% 0805; AGILE_PN: 470-76034; CAD_APPROVED: Yes; FPLIST: RC0805_OV,RC0805,0805_CC; HEIGHT: 0.65MM; MFG_NAME01: BOURNS; MFG_PN01: CRL0805-FW-2R20ELF; ROHS: Yes; Tolerance: 1%
R537 = RES: RES MF 10.0K 1/8W 0.1% 0805; AGILE_PN: 470-80065; CAD_APPROVED: Yes; FPLIST: RC0805_OV,RC0805,0805_CC; HEIGHT: 0.65 MM; MFG_NAME01: BOURNS; MFG_PN01: CRT0805-BY-1002ELF; ROHS: Yes; Tolerance: 0.1%
R538 = RES: RES MF 4.7K 1/10W 5% 0603; AGILE_PN: 470-75414; CAD_APPROVED: Yes; FPLIST: RC0603_OV,RC0603,0603_CC; HEIGHT: 0.55 MM; MFG_NAME01: VISHAY INTERTECHNOLOGY; MFG_PN01: CRCW06034K70JNEA; ROHS: Yes; Tolerance: 5%
U15 = SPX3819M5_FIX_5P: IC VREG LDO 3.3V 500MA 2.5-16V SOT-23-5; AGILE_PN: 315-79574; CAD_APPROVED: Yes; HEIGHT: 1.45 MM; MFG_NAME01: EXAR; ROHS: Yes
U19 = UJA1169TKF: IC XCVR CAN/FD SBC 5V AEC-Q100 HVSON20; AGILE_PN: 315-80898; CAD_APPROVED: Yes; HEIGHT: 1 MM; MFG_NAME01: NXP SEMICONDUCTORS; MFG_PN01: UJA1169TK/FZ; ROHS: Yes
U21 = TJA1027T_8P: IC XCVR LIN 5-18V AEC-Q100 SOIC8; AGILE_PN: 312-81255; CAD_APPROVED: Yes; HEIGHT: 1.75MM; MFG_NAME01: NXP SEMICONDUCTORS; MFG_PN01: TJA1027T/20,118; ROHS: Yes
C5 = CAP_NP: CAP CER 0.1UF 10V 10% X5R 0402; AGILE_PN: 150-75634; CAD_APPROVED: Yes; FPLIST: CC0402_25,CC0402_HD,0402_CC; HEIGHT: 0.64MM; MFG_NAME01: KEMET; MFG_PN01: C0402C104K8PAC; ROHS: Yes; SIGNAL_MODEL: DEFAULT_CAPACITOR_100000pF_2_1; TOL: 10%; Tolerance: 10%; VOLTAGE: 10V
C16 C28 = CAP_NP: CAP CER 0.1UF 10V 10% X5R 0402; AGILE_PN: 150-75634; CAD_APPROVED: Yes; FPLIST: CC0402_25,CC0402_HD,0402_CC; HEIGHT: 0.64MM; MFG_NAME01: KEMET; MFG_PN01: C0402C104K8PAC; PRIORITY_PN: 021-00169; ROHS: Yes; SIGNAL_MODEL: DEFAULT_CAPACITOR_100000pF_2_1; Tolerance: 10%; VOLTAGE: 10V
C126 C127 = CAP_NP: CAP CER 12PF 50V 5% C0G 0402; AGILE_PN: 150-75680; CAD_APPROVED: Yes; FPLIST: CC0402_25,CC0402_HD,0402_CC; HEIGHT: 0.55MM; MFG_NAME01: NIC COMPONENTS CORP; MFG_PN01: NMC0402NPO120J50TRPF; ROHS: Yes; Tolerance: 5%; VOLTAGE: 50V
C533 C535 = CAP_NP: CAP CER 10PF 50V 10% X7R 0603; AGILE_PN: 150-78432; CAD_APPROVED: Yes; FPLIST: CC0603_OV,CC0603,0603_CC; HEIGHT: 0.9MM; MFG_NAME01: AVX; MFG_PN01: 06035C100KAT2A; ROHS: Yes; TOL: 10%; Tolerance: 10%; VOLTAGE: 50V
D11 = LED_TRI_COLOR: LED RED/GRN/BL SGL 3-IN-1 50mA SMT; AGILE_PN: 370-76661; CAD_APPROVED: Yes; HEIGHT: 2.6 MM; MFG_NAME01: Cree, Inc; MFG_PN01: CLP6C-FKB-CM1Q1H1BB7R3R3; ROHS: Yes
J1 J3 J4 = HDR_2X8_M: CON 2X8 SKT TH 100MIL SP 335H AU 104L; AGILE_PN: 210-78860; CAD_APPROVED: Yes; HEIGHT: 8.76MM; MFG_NAME01: SAMTEC; MFG_PN01: SSW-108-01-S-D; ROHS: Yes
J2 J5 J6 = CONN_HDR_10X2: CON 2X10 SKT TH 100MIL CTR 340H AU 104L; AGILE_PN: 210-80119; CAD_APPROVED: Yes; HEIGHT: 8.64MM; MFG_NAME01: SAMTEC; MFG_PN01: SSW-110-01-G-D; ROHS: Yes
R13 = POT: RES POT 5K 1/2W 20% TH; AGILE_PN: 470-80115; CAD_APPROVED: Yes; HEIGHT: 4.32 MM; MFG_NAME01: BOURNS; MFG_PN01: 3352T-1-502LF; ROHS: Yes; TOL: 20%; Tolerance: 20%
R91 = RES: RES MF 1.0M 1/10W 1% 0603; AGILE_PN: 470-76249; CAD_APPROVED: Yes; FPLIST: RC0603_OV,RC0603,0603_CC; HEIGHT: 0.6mm; MFG_NAME01: WALSIN TECHNOLOGY CORP.; MFG_PN01: WR06X1004FTL; ROHS: Yes; Tolerance: 1%
R95-R97 = RES: RES MF 220 OHM 1/10W 5% 0603; AGILE_PN: 470-30297; CAD_APPROVED: Yes; FPLIST: RC0603_OV,RC0603,0603_CC; HEIGHT: 0.6MM; MFG_NAME01: YAGEO AMERICA; MFG_PN01: RC0603JR-07220RL; ROHS: Yes; Tolerance: 5%
R525 R528 = RES: RES MF 4.7K 1/10W 0.1% AEC-Q200 0603; AGILE_PN: 470-80811; CAD_APPROVED: Yes; FPLIST: RC0603_OV,RC0603,0603_CC; HEIGHT: 0.55MM; MFG_NAME01: YAGEO AMERICA; MFG_PN01: AT0603BRD074K7L; ROHS: Yes; Tolerance: 0.1%
SW7 SW8 = ELECTRODE: Capacitive Single Electrode 15MM x 15MM (not a part to order); AGILE_PN: 510-76938; CAD_APPROVED: Yes; FPLIST: electrode_sq_15mm,electrode_sq_15mm_cust; HEIGHT: 0MM; MFG_NAME01: Freescale; MFG_PN01: Single Electrode 15MM x 15MM; ROHS: Yes
Y3 = XTAL: XTAL 8MHZ 8pF AEC-Q200 SMD; AGILE_PN: 230-77981; CAD_APPROVED: Yes; HEIGHT: 1MM; MFG_NAME01: NDK; MFG_PN01: NX3225GD-8MHZ-STD-CRA-3; ROHS: Yes

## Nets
GND: C1.2 C2.2 C3.2 C4.2 C5.2 C6.2 C7.2 C8.2 C9.2 C10.2 C11.2 C12.2 C16.2 C17.2 C18.2 C19.2 C20.2 C21.2 C22.2 C23.2 C24.2 C25.2 C26.2 C27.2 C28.2 C29.2 C40.2 C43.2 C47.2 C49.2 C59.2 C126.2 C127.2 C128.2 C129.2 C131.2 C133.2 C137.2 C140.2 C141.2 C142.2 C143.2 C144.2 C145.2 C146.2 C147.2 C148.2 C533.2 C535.2 C536.2 C537.2 C538.2 D3.C(CATHODE) D7.A(ANODE) D17.1(C1) D18.1(C1) D19.1(C1) J2.13 J3.11 J3.13 J5.12 J6.12 J7.5(GND) J11.4 J12.3(A2) J12.5(A3) J13.4 J14.3(A2) J14.5(A3) J16.2 J16.3 J16.SH1(SHIELD1) J16.SH2(SHIELD2) L2.2 R13.3(B) R16.2 R20.2 R31.2 R44.2 R51.2 R62.2 R68.2 R74.2 R170.1 SW5.1 SW5.3 SW9.2 SW9.4 TP1.1(Pin1) TP17.1(Pin1) TP32.1(Pin1) U1.4(GND) U2.3(DIR) U2.4(GND) U4.2(GND) U7.2(GND) U8.2(VSS1) U8.8(VSSA) U8.33(EPAD) U9.2(GND) U10.2(GND) U11.2(GND) U15.2(GND) U17.13(VREFL) U17.14(VSS1) U17.37(VSS2) U17.60(VSS3) U17.86(VSS4) U19.1(GND1) U19.4(GND2) U19.16(GND3) U19.19(GND4) U19.21(EP) U21.5(GND) U26.4(GND) U28.4(GND) U29.2(GND) U30.4(GND) U31.2(GND) U31.5(DIR) U32.4(GND) U33.2(GND) Y1.2
P3V3: C24.1 J3.7 J10.1 R63.1 TP13.1(Pin1) U15.5(VOUT)
P3V3_SDA: C3.1 C6.1 C7.1 C10.1 C12.1 C18.1 C19.1 C26.1 J9.1 J12.1(A1) R1.2 R3.1 R12.1 R15.1 R30.1 R39.2 R42.1 R52.1 R60.1 R77.1 U1.1(VCCA) U2.7(VCCA) U4.1(VCCA) U7.1(VCCA) U8.1(VDD1) U8.7(VDDA) U8.11(VBAT) U9.5(VCC) U10.1(VCCA)
P5V0: C21.1 C22.1 J3.9 J10.3 J107.2 R64.1 R169.1 TP14.1(Pin1) U15.1(VIN)
P5V0_SDA_USB_CONN_VBUS: D17.2(C2) J7.1(VBUS) L1.1
P5V_SBC: C27.1 C538.1 J107.3 R530.1 R535.1 R536.1 R538.1 R556.2 R558.2 R559.1 R560.2 R562.2 R564.1 TP15.1(Pin1) U19.5(V1) U26.1(VCCA) U28.1(VCCA) U29.1(VCCA) U30.1(VCCA) U31.1(VCCA) U32.1(VCCA) U33.1(VCCA)
P5V_SDA: C11.1 C15.1 C25.1 L1.2 R14.1 R57.1 R70.1 U8.6(VREGIN) U11.1(VIN)
P5V_SDA_PSW: J107.1 U11.6(VOUT)
VBATT: D9.A(ANODE) J11.2 J16.1 TP38.1(Pin1)
VDD: C49.1 C537.1 D11.A1(ANODE1) D11.A2(ANODE2) D11.A3(ANODE3) J3.3 J5.10 J6.10 J10.2 J14.1(A1) J15.2 R13.1(A) R56.2 R63.2 R64.2 R117.1 R121.1 SH1.2 SW2.2 SW2.4 SW3.2 SW3.4 TP4.1(Pin1) TP9.1(Pin1) TP16.1(Pin1) U26.8(VCCB) U28.8(VCCB) U29.6(VCCB) U30.8(VCCB) U31.6(VCCB) U32.8(VCCB) U33.6(VCCB)
VDD_MCU: C43.1 C129.1 C131.1 C133.1 C137.1 C140.1 C141.1 C142.1 C143.1 C144.1 C145.1 C146.1 C147.1 J15.1 R99.1 R103.1 R117.2 U17.10(VDD1) U17.11(VDDA) U17.38(VDD2) U17.61(VDD3) U17.87(VDD4)
VIN: D13.A(ANODE) J3.1 J3.15
ADC0_SE12: C5.1 R13.2(WIPER) R164.2 TP5.1(Pin1)
AREF: J2.15 R109.2
BTN0: C16.1 R44.1 R152.2 SW2.1 SW2.3
BTN1: C28.1 R74.1 R153.2 SW3.1 SW3.3
CAN_HI: J13.1 J109.1 TP19.1(Pin1) U19.18(CANH)
JTAG_TCLK/SWD_CLK: J8.2 J14.4(B2) R127.2 TP31.1(Pin1)
JTAG_TDI: R120.2 R128.2
JTAG_TDO: R119.2 R123.2
JTAG_TMS/SWD_DIO_PTA4: J14.2(B1) J106.2 R121.2 R122.2 TP34.1(Pin1)
LEDRGB_BLUE: D11.C3(CATHODE3) R95.1 TP28.1(Pin1)
LEDRGB_GREEN: D11.C2(CATHODE2) R96.1 TP29.1(Pin1)
LEDRGB_RED: D11.C1(CATHODE1) R97.1 TP30.1(Pin1)
LIN: C17.1 J11.1 R80.2 R171.2 TP18.1(Pin1) U21.6(LIN)
LIN_RX: R130.1 U28.7(B1)
LIN_RX_LS: R538.2 TP35.1(Pin1) U21.1(RXD) U28.2(A1)
LIN_SLP: R529.1 R530.2 U21.2(~{SLP})
LIN_TX: R131.1 U28.6(B2)
LIN_TX_LS: TP37.1(Pin1) U21.4(TXD) U28.3(A2)
LVLRST_EN: R1.1 U1.5(OE)
MIC2005_CSLEW: C15.2 U11.5(CSLEW)
POWER_EN: R69.2 U8.31(ADC0_SE7B/PTD6/SPI0_PCS3/UART0_RX/FTM0_CH6/FTM0_FLT0/LLWU_P15)
PTA0: J5.7 U17.79(PTA0/ADC0_SE0/ACMP0_IN0/FTM2_CH1/LPI2C0_SCLS/FXIO_D2/FTM2_QD_PHA/LPUART0_CTS/TRGMUX_OUT3)
PTA1: J5.5 U17.78(PTA1/ADC0_SE1/ACMP0_IN1/FTM1_CH1/LPI2C0_SDAS/FXIO_D3/FTM1_QD_PHA/LPUART0_RTS/TRGMUX_OUT0)
PTA2: R540.2 R542.1 SH11.1 U17.73(PTA2/ADC1_SE0/FTM3_CH0/LPI2C0_SDA/~{EWM_OUT}/LPUART0_RX)
PTA3: R539.2 R541.1 SH12.1 U17.72(PTA3/ADC1_SE1/FTM3_CH1/LPI2C0_SCL/EWM_IN/LPUART0_TX)
PTA4: R122.1 R546.2 U17.98(PTA4/ACMP0_OUT/~{EWM_OUT}/JTAG_TMS/SWD_DIO)
PTA6: R147.2 U17.58(PTA6/ADC0_SE2/ACMP1_IN0/FTM0_FLT1/LPSPI1_PCS1/LPUART1_CTS)
PTA7: J5.9 U17.57(PTA7/ADC0_SE3/ACMP1_IN1/FTM0_FLT2/RTC_CLKIN/LPUART1_RTS)
PTA8: J6.17 U17.100(PTA8/LPUART3_RX/LPSPI2_SOUT/FXIO_D6/FTM3_FLT3)
PTA9: J6.19 U17.99(PTA9/LPUART3_TX/LPSPI2_PCS0/FXIO_D7/FTM3_FLT2/FTM1_FLT3)
PTA10: R123.1 R545.2 U17.92(PTA10/FTM1_CH4/FXIO_D0/JTAG_TDO/NOETM_TRACE_SWO)
PTA11: J1.2 U17.91(PTA11/FTM1_CH5/FXIO_D1)
PTA12: J6.16 U17.90(PTA12/FTM1_CH6/CAN1_RX/LPI2C1_SDAS)
PTA13: J6.14 U17.89(PTA13/FTM1_CH7/CAN1_TX/LPI2C1_SCLS)
PTA14: J2.16 U17.88(PTA14/FTM0_FLT0/FTM3_FLT1/EWM_IN/FTM1_FLT0/BUSOUT)
PTA15: R167.1 U17.83(PTA15/ADC1_SE12/FTM1_CH2/LPSPI0_PCS3/LPSPI2_PCS3)
PTA16: R165.1 U17.82(PTA16/ADC1_SE13/FTM1_CH3/LPSPI1_PCS2)
PTA17: J1.4 U17.62(PTA17/FTM0_CH6/FTM3_FLT0/~{EWM_OUT})
PTB0: J4.5 U17.54(PTB0/ADC0_SE4/LPUART0_RX/LPSPI0_PCS0/LPTMR0_ALT3)
PTB1: J4.7 U17.53(PTB1/ADC0_SE5/LPUART0_TX/LPSPI0_SOUT/TCLK0)
PTB2: J2.11 U17.48(PTB2/ADC0_SE6/FTM1_CH0/LPSPI0_SCK/FTM1_QD_PHB/TRGMUX_IN3)
PTB3: J2.9 U17.47(PTB3/ADC0_SE7/FTM1_CH1/LPSPI0_SIN/FTM1_QD_PHA/TRGMUX_IN2)
PTB4: J2.7 U17.28(PTB4/ACMP1_IN2/FTM0_CH4/LPSPI0_SOUT/TRGMUX_IN1/HDPIN1)
PTB5: J2.5 U17.27(PTB5/FTM0_CH5/LPSPI0_PCS1/TRGMUX_IN0/ACMPX_OUT2/HDPIN2)
PTB6: R81.2 R84.1 U17.16(PTB6/XTAL/LPI2C0_SDA)
PTB6_XTAL: C127.1 R84.2 R91.2 Y3.2
PTB7: R88.1 R90.2 U17.15(PTB7/EXTAL/LPI2C0_SCL)
PTB7_EXTAL: C126.1 R88.2 R91.1 Y3.1
PTB8: J1.5 U17.77(PTB8/FTM3_CH0)
PTB9: J1.7 U17.76(PTB9/FTM3_CH1/LPI2C0_SCLS)
PTB10: J1.9 U17.75(PTB10/FTM3_CH2/LPI2C0_SDAS)
PTB11: J1.11 U17.74(PTB11/FTM3_CH3/LPI2C0_HREQ)
PTB12: J4.3 U17.68(PTB12/ADC1_SE7/FTM0_CH0/FTM3_FLT2/CAN2_RX)
PTB13: J5.11 U17.67(PTB13/ADC1_SE8/FTM0_CH1/FTM3_FLT1/CAN2_TX)
PTB14: J4.8 R124.1 U17.66(PTB14/ADC1_SE9/FTM0_CH2/LPSPI1_SCK)
PTB15: J4.10 R125.1 U17.65(PTB15/ADC1_SE14/FTM0_CH3/LPSPI1_SIN)
PTB16: J4.12 R126.1 U17.64(PTB16/ADC1_SE15/FTM0_CH4/LPSPI1_SOUT)
PTB17: J4.6 R129.1 U17.63(PTB17/FTM0_CH5/LPSPI1_PCS3)
PTC0: R146.2 R534.1 U17.40(PTC0/ADC0_SE8/ACMP1_IN4/FTM0_CH0/FTM1_CH6)
PTC1: J5.13 R172.2 R525.2 U17.39(PTC1/ADC0_SE9/ACMP1_IN3/FTM0_CH1/FTM1_CH7)
PTC2: J5.15 R527.2 R528.2 U17.30(PTC2/ADC0_SE10/ACMP0_IN5/FTM0_CH2/CAN0_RX)
PTC3: J4.16 R132.2 R533.1 U17.29(PTC3/ADC0_SE11/ACMP0_IN4/FTM0_CH3/CAN0_TX)
PTC4: J3.12 R127.1 U17.96(PTC4/JTAG_TCLK/SWD_CLK/ACMP0_IN2/FTM1_CH0/RTC_CLKOUT/EWM_IN/FTM1_QD_PHB)
PTC5: J3.10 R128.1 U17.95(PTC5/FTM2_CH0/RTC_CLKOUT/LPI2C1_HREQ/FTM2_QD_PHB/JTAG_TDI)
PTC6: J4.4 R161.1 U17.81(PTC6/ADC1_SE4/LPUART1_RX/CAN1_RX/FTM3_CH2)
PTC7: J4.2 R162.1 U17.80(PTC7/ADC1_SE5/LPUART1_TX/CAN1_TX/FTM3_CH3)
PTC8: J6.9 U17.56(PTC8/LPUART1_RX/FTM1_FLT0/LPUART0_CTS)
PTC9: J6.11 U17.55(PTC9/LPUART1_TX/FTM1_FLT1/LPUART0_RTS)
PTC10: R133.2 U17.52(PTC10/FTM3_CH4/TRGMUX_IN11)
PTC11: R134.2 U17.51(PTC11/FTM3_CH5/TRGMUX_IN10)
PTC12: J2.10 R152.1 U17.50(PTC12/FTM3_CH6/FTM2_CH6/LPUART3_CTS)
PTC13: J2.12 R153.1 U17.49(PTC13/FTM3_CH7/FTM2_CH7/LPUART3_RTS)
PTC14: J4.14 R164.1 U17.46(PTC14/ADC0_SE12/FTM1_CH2/TRGMUX_IN9)
PTC15: J5.20 U17.45(PTC15/ADC0_SE13/FTM1_CH3/TRGMUX_IN8)
PTC16: J6.8 U17.44(PTC16/ADC0_SE14/FTM1_FLT2/CAN2_RX/LPI2C1_SDAS)
PTC17: J6.6 U17.43(PTC17/ADC0_SE15/FTM1_FLT3/CAN2_TX/LPI2C1_SCLS)
PTD0: J2.6 J6.1 R156.1 U17.4(PTD0/FTM0_CH2/LPSPI1_SCK/FTM2_CH0/FXIO_D0/TRGMUX_OUT1/HDPIN)
PTD1: J6.2 U17.3(PTD1/FTM0_CH3/LPSPI1_SIN/FTM2_CH1/FXIO_D1/TRGMUX_OUT2/HDPIN)
PTD2: SH13.2 U17.71(PTD2/ADC1_SE2/FTM3_CH4/LPSPI1_SOUT/FXIO_D4/TRGMUX_IN5)
PTD3: J1.14 J6.4 U17.70(PTD3/ADC1_SE3/FTM3_CH5/LPSPI1_PCS0/FXIO_D5/TRGMUX_IN4/~{NMI})
PTD4: J4.1 U17.69(PTD4/ADC1_SE6/FTM0_FLT3/FTM3_FLT3)
PTD5: J1.12 U17.33(PTD5/FTM2_CH3/LPTMR0_ALT2/FTM2_FLT1/TRGMUX_IN7)
PTD6: J5.18 R130.2 U17.32(PTD6/ACMP0_IN7/LPUART2_RX/FTM2_FLT2)
PTD7: J5.16 R131.2 U17.31(PTD7/ACMP0_IN6/LPUART2_TX/FTM2_FLT3)
PTD8: J6.7 U17.42(PTD8/LPI2C1_SDA/FTM2_FLT2/FTM1_CH4)
PTD9: J6.5 U17.41(PTD9/LPI2C1_SCL/FTM2_FLT3/FTM1_CH5)
PTD10: J1.6 R166.1 U17.36(PTD10/FTM2_CH0/FTM2_QD_PHB)
PTD11: J1.8 R168.1 U17.35(PTD11/FTM2_CH1/FTM2_QD_PHA/LPUART2_CTS)
PTD12: J1.10 U17.34(PTD12/FTM2_CH2/LPI2C1_HREQ/LPUART2_RTS)
PTD13: J2.1 U17.25(PTD13/FTM2_CH4/LPUART3_RX/RTC_CLKOUT)
PTD14: J2.3 U17.24(PTD14/FTM2_CH5/LPUART3_TX/CLKOUT)
PTD15: J2.2 R154.2 U17.22(PTD15/FTM0_CH0/HDPIN)
PTD16: J2.4 R155.2 U17.21(PTD16/FTM0_CH1/HDPIN)
PTD17: J6.13 U17.20(PTD17/FTM0_FLT2/LPUART2_RX)
PTE0: J3.6 U17.94(PTE0/LPSPI0_SCK/TCLK1/LPI2C1_SDA/FTM1_FLT2/HDPIN)
PTE1: J5.14 U17.93(PTE1/LPSPI0_SIN/LPI2C0_HREQ/LPI2C1_SCL/FTM1_FLT1/HDPIN)
PTE2: J4.13 U17.85(PTE2/ADC1_SE10/LPSPI0_SOUT/LPTMR0_ALT3/FTM3_CH6/LPUART1_CTS)
PTE3: J1.16 U17.18(PTE3/FTM0_FLT0/LPUART2_RTS/FTM2_FLT0/TRGMUX_IN6/ACMPX_OUT1)
PTE4: J6.20 R137.2 U17.9(PTE4/BUSOUT/FTM2_QD_PHB/FTM2_CH2/CAN0_RX/FXIO_D6/~{EWM_OUT})
PTE5: J6.18 R136.2 U17.8(PTE5/TCLK2/FTM2_QD_PHA/FTM2_CH3/CAN0_TX/FXIO_D7/EWM_IN)
PTE6: J4.15 U17.84(PTE6/ADC1_SE11/LPSPI0_PCS2/FTM3_CH7/LPUART1_RTS)
PTE7: J2.14 U17.59(PTE7/FTM0_CH7/FTM3_FLT0)
PTE8: J2.8 R135.2 U17.26(PTE8/ACMP0_IN3/FTM0_CH6)
PTE9: J3.8 R529.2 U17.23(PTE9/FTM0_CH7/LPUART2_CTS)
PTE10: R543.1 R567.2 U17.6(PTE10/CLKOUT/LPSPI2_PCS1/FTM2_CH4/FXIO_D4/TRGMUX_OUT4)
PTE11: R544.1 R568.2 U17.5(PTE11/LPTMR0_ALT1/FTM2_CH5/FXIO_D5/TRGMUX_OUT5)
PTE12: J6.15 U17.19(PTE12/FTM0_FLT3/LPUART2_TX)
PTE13: J5.8 R532.2 U17.7(PTE13/LPSPI2_PCS2/FTM2_FLT0)
PTE14: J5.6 U17.17(PTE14/FTM0_FLT1/FTM2_FLT1)
PTE15: J5.4 U17.2(PTE15/LPUART3_CTS/LPSPI2_SCK/FTM2_CH6/FXIO_D2/TRGMUX_OUT6)
PTE16: J5.2 U17.1(PTE16/LPUART3_RTS/LPSPI2_SIN/FTM2_CH7/FXIO_D3/TRGMUX_OUT7)
PWR_LED: D3.A(ANODE) R56.1
RGB_BLUE: R95.2 R156.2
RGB_GREEN: R96.2 R155.1
RGB_RED: R97.2 R154.1
RST_TGTMCU_B: D1.C(CATHODE) J3.5 J14.10(B5) J104.3 R4.2 R5.2 R563.2 U1.7(B1) U17.97(PTA5/TCLK1/~{JTAG_TRST}/~{RESET})
SBC_CAN_RX: R137.1 U30.6(B2)
SBC_CAN_RX_LS: TP20.1(Pin1) U19.7(RXD) U30.3(A2)
SBC_CAN_TX: R136.1 U30.7(B1)
SBC_CAN_TX_LS: TP21.1(Pin1) U19.2(TXD) U30.2(A1)
SBC_CS: R129.2 U31.4(B)
SBC_CS_LS: TP33.1(Pin1) U19.20(~{SCS}) U31.3(A)
SBC_LIMP: R532.1 U33.4(B)
SBC_LIMP_LS: R536.2 R566.1 TP502.1(Pin1) U19.11(~{LIMP})
SBC_MISO: R125.2 U29.4(B)
SBC_MISO_LS: TP23.1(Pin1) U19.9(SDO) U29.3(A)
SBC_MOSI: R126.2 U26.6(B2)
SBC_MOSI_LS: TP25.1(Pin1) U19.3(SDI) U26.3(A2)
SBC_RST: R565.1 TP24.1(Pin1) U19.8(~{RST})
SBC_SCK: R124.2 U26.7(B1)
SBC_SCK_LS: TP27.1(Pin1) U19.10(SCK) U26.2(A1)
SDA_EXTAL: C23.1 U8.17(EXTAL0/PTA18/FTM0_FLT2/FTM_CLKIN0) Y1.3
SDA_JTAG_TCLK: J12.4(B2) U8.12(JTAG_TCLK/SWD_CLK/EZP_CLK/TSI0_CH1/PTA0/~{UART0_CTS}/~{UART0_COL}/FTM0_CH5)
SDA_JTAG_TDI: J12.8(B4) U8.13(JTAG_TDI/EZP_DI/TSI0_CH2/PTA1/UART0_RX/FTM0_CH6)
SDA_JTAG_TDO: J12.6(B3) U8.14(JTAG_TDO/TRACE_SWO/EZP_DO/TSI0_CH3/PTA2/UART0_TX/FTM0_CH7)
SDA_JTAG_TMS: J12.2(B1) R77.2 U8.15(JTAG_TMS/SWD_DIO/TSI0_CH4/PTA3/~{UART0_RTS}/FTM0_CH0)
SDA_LED: D2.C(CATHODE) U8.29(PTD4/SPI0_PCS1/~{UART0_RTS}/FTM0_CH4/EWM_IN/LLWU_P14)
SDA_LED_R: D2.A(ANODE) R12.2
SDA_RST: J12.10(B5) R57.2 R62.1 TP12.1(Pin1) U8.19(~{RESET})
SDA_RST_LED: D1.A(ANODE) R2.1
SDA_RST_TGTMCU_B: J105.2 U8.21(ADC0_SE9/TSI0_CH6/PTB1/I2C0_SDA/FTM1_CH1/FTM1_QD_PHB)
SDA_RST_TGTMCU_J_B: J104.1 J105.1 R3.2 R5.1 U1.2(A1)
SDA_RX_EN: R15.2 R16.1 U4.5(DIR)
SDA_SPI0_CS: R38.2 TP7.1(Pin1) U8.23(ADC0_SE4B/CMP1_IN0/TSI0_CH15/PTC2/SPI0_PCS2/~{UART1_CTS}/FTM0_CH1/I2S0_TX_FS)
SDA_SPI0_RST_B: R41.2 TP8.1(Pin1) U8.22(ADC0_SE15/TSI0_CH14/PTC1/SPI0_PCS3/~{UART1_RTS}/FTM0_CH0/I2S0_TXD0/LLWU_P6)
SDA_SPI0_SCK: U8.26(PTC5/SPI0_SCK/LPTMR0_ALT2/I2S0_RXD0/CMP0_OUT/LLWU_P9) U10.3(A)
SDA_SPI0_SIN: U2.5(2A) U8.28(CMP0_IN1/PTC7/SPI0_SIN/USB_SOF_OUT/I2S0_RX_FS)
SDA_SPI0_SOUT: U7.3(A) U8.27(CMP0_IN0/PTC6/SPI0_SOUT/PDB0_EXTRG/I2S0_RX_BCLK/I2S0_MCLK/LLWU_P10)
SDA_SWD_EN: R41.1 R47.1 U9.6(Y1)
SDA_SWD_EN_B: R49.2 U8.16(~{NMI}/~{EZP_CS}/TSI0_CH5/PTA4/FTM0_CH1/LLWU_P3)
SDA_SWD_EN_B_R: R42.2 R49.1 U9.1(A1)
SDA_SWD_EN_R: R47.2 R51.1 R52.2 U10.5(DIR)
SDA_SWD_OE: R35.1 R38.1 U9.4(Y2)
SDA_SWD_OE_B: R32.2 U8.20(ADC0_SE8/TSI0_CH0/PTB0/I2C0_SCL/FTM1_CH0/FTM1_QD_PHA/LLWU_P5)
SDA_SWD_OE_B_R: R32.1 R39.1 U9.3(A2)
SDA_SWD_OE_R: R30.2 R31.1 R35.2 U7.5(DIR)
SDA_USB_CONN_DN: D19.2(C2) J7.2(D-) R25.1
SDA_USB_CONN_DP: D18.2(C2) J7.3(D+) R21.1
SDA_USB_DN: R25.2 U8.4(USB0_DM)
SDA_USB_DP: R21.2 U8.3(USB0_DP)
SDA_USB_P5V_SENSE: R14.2 R20.1 U8.30(ADC0_SE6B/PTD5/SPI0_PCS2/~{UART0_CTS}/~{UART0_COL}/FTM0_CH5/~{EWM_OUT})
SDA_USBSHIELD: J7.6(SHELL1) J7.7(SHELL2) J7.8(SHELL3) J7.9(SHELL4) J7.10(SHELL5) L2.1
SDA_VOUT33: C9.1 J9.2 U8.5(VOUT33)
SDA_XTAL: C20.1 U8.18(XTAL0/PTA19/FTM1_FLT0/FTM_CLKIN1/LPTMR0_ALT1) Y1.1
SW1_RST_B: C1.1 J104.2 SW5.2 SW5.4
SWD_CLK_TGTMCU_BUF: J8.1 U10.4(B)
SWD_DIO_TGTMCU_BUF: J106.1 U2.2(2B) U7.4(B)
TC_EXTAL_TP: TP11.1(Pin1) U8.10(EXTAL32)
TC_SDA_USB_ID_TP: J7.4(ID) TP6.1(Pin1)
TC_XTAL_TP: TP10.1(Pin1) U8.9(XTAL32)
TP_2102_A: TP500.1(Pin1) U1.3(A2)
TP_2102_B: TP501.1(Pin1) U1.6(B2)
UART1_RX_TGTMCU_BUF: R24.1 U4.4(B)
UART1_RX_TGTMCU_R: U4.3(A) U8.25(PTC4/SPI0_PCS0/UART1_TX/FTM0_CH3/CMP1_OUT/LLWU_P8)
UART1_TX_TGTMCU_BUF: R18.1 U2.1(1B)
UART1_TX_TGTMCU_R: U2.6(1A) U8.24(CMP1_IN1/PTC3/SPI0_PCS1/UART1_RX/FTM0_CH2/I2S0_TX_BCLK/LLWU_P7)
UART_RX: R24.2 R161.2
UART_TX: R18.2 R162.2
V_TGTMCU: C2.1 C4.1 C8.1 R2.2 R4.1 SH1.1 U1.8(VCCB) U2.8(VCCB) U4.6(VCCB) U7.6(VCCB) U10.6(VCCB)
VREFH: C148.1 D7.C(CATHODE) R99.2 R103.2 R109.1 U17.12(VREFH)
VSUP: C29.1 C47.1 C128.1 D6.A D9.C(CATHODE) D13.C(CATHODE) Q1.1(Emitter1) Q1.2(Emitter2) Q1.3(Emitter3) R537.1 TP36.1(Pin1) U19.14(BAT) U21.7(VBAT)
VTRG_EN: R68.1 R69.1 R70.2 U11.3(ENABLE)
VTRG_FAULT_B: R60.2 U8.32(PTD7/CMT_IRO/UART0_TX/FTM0_CH7/FTM0_FLT1) U11.4(~{FAULT})
N20328118: J13.2 J108.1 TP22.1(Pin1) U19.17(CANL)
N20337946: J5.3 R165.2 R166.2
N20338949: J5.1 R167.2 R168.2
N20340793: J6.3 SH13.1
N20341657: J1.13 R132.1 R133.1
N20341806: J1.15 R134.1 R135.1
N20342040: J2.19 R539.1 R567.1
N20342083: J2.17 R540.1 R568.1
N20344687: J4.11 R146.1 R541.2 R543.2
N20344693: J4.9 R147.1 R542.2 R544.2
N20408163: R169.2 R170.2 U15.3(EN)
N20408770: C59.1 U15.4(BYP)
N20447644: J1.1 SH11.2
N20447648: J1.3 SH12.2
N20483325: J3.2 R81.1
N20483330: J3.4 R90.1
N20483362: J3.14 R545.1
N20483368: J3.16 R546.1
N20487643: C533.1 R525.1 R533.2
N20487701: R527.1 SW8.1
N20487722: C535.1 R528.1 R534.2
N20498074: Q1.4(Base) U19.15(VEXCTRL)
N20519466: C536.1 U19.13(V2)
N20520251: R537.2 SW9.1 SW9.3 U19.12(WAKE)
N20529258: D6.C R80.1 R171.1
N20532266: Q1.5(Collector) R535.2 U19.6(VEXCC)
N20533540: R172.1 SW7.1
N20615890: R556.1 U26.5(OE)
N20616554: R558.1 U28.5(OE)
N20618570: R559.2 U29.5(DIR)
N20622415: R560.1 U30.5(OE)
N20627960: R562.1 U32.5(OE)
N20628442: R563.1 U32.7(B1)
N20629363: R564.2 U33.5(DIR)
N20629726: R565.2 U32.2(A1)
N20631005: R566.2 U33.3(A)
N20723757: J14.6(B3) R119.1
N20723759: J14.8(B4) R120.1
N20797624: J109.2 R92.2
N20797631: J108.2 R98.2
N20797648: C40.1 R92.1 R98.1

Not connected (* = marked no-connect by the designer): J2 18* 20*; J5 17* 19*; J11 3*; J12 7(A4)* 9(A5)*; J13 3*; J14 7(A4)* 9(A5)*; U21 3(NC1)* 8(NC2)*; U32 3(A2)* 6(B2)*

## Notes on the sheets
sheet 1
- OpenSDA Interface
- Reset
- 1-2: Default.
  2-3: Reset signal direct to the MCU,
  to use when OpenSDA is not powered.
- RST Push Button
  Bypass
- Target MCU
  Interface
  Signals
- Output to system
  from Level shifter
- UART1_RX_TGTMCU
- PU/PD LOGIC:
  SERIAL INTERFACE
  IS ALWAYS RESET
  WHEN USB PORT
  IS DISCONNECTED
- Isolation
  Resistors
- Output to system
  from Level shifter
- UART1_TX_TGTMCU
- Output to system
  from Level shifter
- SWD_DIO_TGTMCU
- HW Designer: Rafael del Rey
- Open SDA
  Input Power
- Ope SDA
  Power Outputs
- i
- path
- i
- path
- OpenSDA Interface JTAG Connector
- PWR Switch
- (To enable 5v from
  USB connector)
- Note: You can power openSDA
  with your own power supplies
  by replacing this rail
  (SDA_VOUT33)
  with your 3.3V power supply rail
- 3.3VDC, 10mA should be provided
  to this rail (P3V3_SDA)
  in order to power openSDA
  module
- Isolation and level shift stage
  (for 1.8 to 5V compatibility)
- PU/PD LOGIC (DIR PIN):
  BUFFER IS TRISTATED WHEN
  P3V3_SDA IS UNPOWERED
- SHORTING HEADER ON BOTTOM LAYER
  Jumper is shorted by a cut-trace
  on bottom layer. Cutting the trace
  will effectively isolate the on-board
  MCU from the OpenSDA
  debug interface.
- i
- path
- ACTIVE HIGH
- SDA_VOUT33 can provide up to 120mA
  of power at 3.3VDC to your system
  P5V_TRG_SDA can provide up to 450mA
  (per USB spec) of power at 5VDC
  to your system
- I/O Poer
  Input
- i
- path
- V_BRD is supported
  from 1.8V to 5V
- Power should be provided
  to this rail for the logic
  related to your platform I/O
- {For Enablement Purposes Only}
sheet 2
- MCU Current Measurement
- Power Supply Selection
- SWD Connector - S32K144 Programming
- Note: VREFH can be selected from
  the following 3 options:
  - Option 1(default):  VREFH =
  VDD_MCU, place R103, dnp R99, R109
  and D7.
  - Option 2: VREFH = 3.0V from D7,
  place D7 and R99, dnp R103 and
  R109.
  - Option 3: VREFH=AREF, place R109,
  dnp R103,R99 and D7.
sheet 3
- 1. Unless Otherwise Specified:
- All resistors are in ohms,  1% and 5 %
- All capacitors are in uF,  10% , 20 % and  5%
- All voltages are DC
- All polarized capacitors are aluminum electrolytic
- 2. Interrupted lines coded with the same letter or letter
      combinations are electrically connected.
- 3. Device type number is for reference only. The number
      varies with the manufacturer.
- 4. Special signal usage:
- _B Denotes - Active-Low Signal
- <> or [] Denotes - Vectored Signals
- 5. Interpret diagram in accordance with American
  National Standards Institute specifications, current
  revision, with the exception of logic block symbology.
sheet 4
- Table of Contents
- Revisions
- 2
- Notes and Block Diagram
- Rev
- Description
- Date
- Approved
- 3
- S32K144 MCU
- XA
- Initial Release
- APR-13-2016
- O. Romero
- 4
- OpenSDA interface
- A
- Prototype Production
- APR-14-2016
- O. Romero
- 5
- Power Supply/SWD
- AX1
- Development
- AUG-16-2016
- O. Romero
- 6
- I/O Headers
- B
- 2nd Release
- SEP-02-2016
- O. Romero
- B1
- Update BOM
- DEC-16-2016
- O. Romero
- C
- Update BOM
- MAR-1-2018
- A. Gonzalez
- S32K144EVB-Q100
sheet 5
- CAN Physical Layer
- 3.3V LDO Power Supply
- 20mOhm Resistor
  in layout
- CAN
- CAN_LO
- LIN Physical Layer
- Level Shifters
- MASTER OPTION
- Note: Place R530
  only after R529
  has been
  removed.
sheet 6
- NOTE:
  J1,J2,J3 and J4:  Arduino UNO
  compatible headers.
  J5 and J6: Arduino Mega
  compatible headers.
- Xtal
- NOTE:
  PTA2 and PTA3 I2C via LPI2C
  PTE10 and PTE11 I2C via FLEXIO
- NOTE: J2-15.
  R134, place it by deafult for extra
  GPIO/PWM.
  R135, place it and remove R134 to  have
  CMP functionality.
- NOTE: J2-13.
  R133, place it by deafult for extra
  GPIO/PWM.
  R132, place it  and remove R133 to  have
  CMP functionality.
- Note J5-1:
  R167 place it by defualt for
  ADC channel.
  R168  place it and remove  R167
  when using  FSL BLDC shield.
- NOTE: J4-9, J4-11
  R146, and R147 placed by deafult,
  remove and place R544 and  R543 for
  I2C functionality with FLEXIO or
  place PTA2 and PTA3 for LPI2C .
- Note J5-3:
  R165 place it by defualt for
  ADC channel.
  R166  place it and remove R165
  when  using  FSL BLDC shield.
- Potentiometer
- User Buttons
- Touch Pads
- RGB Led
